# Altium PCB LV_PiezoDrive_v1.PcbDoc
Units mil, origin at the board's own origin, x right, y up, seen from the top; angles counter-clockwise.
Board outline 4800 x 6200 mil, 6 copper layers (Top Layer, Internal Plane 1, Internal Plane 2, Internal Plane 3, Internal Plane 4, Bottom Layer); 156 components, 66 nets, 491 pads, 10 vias.
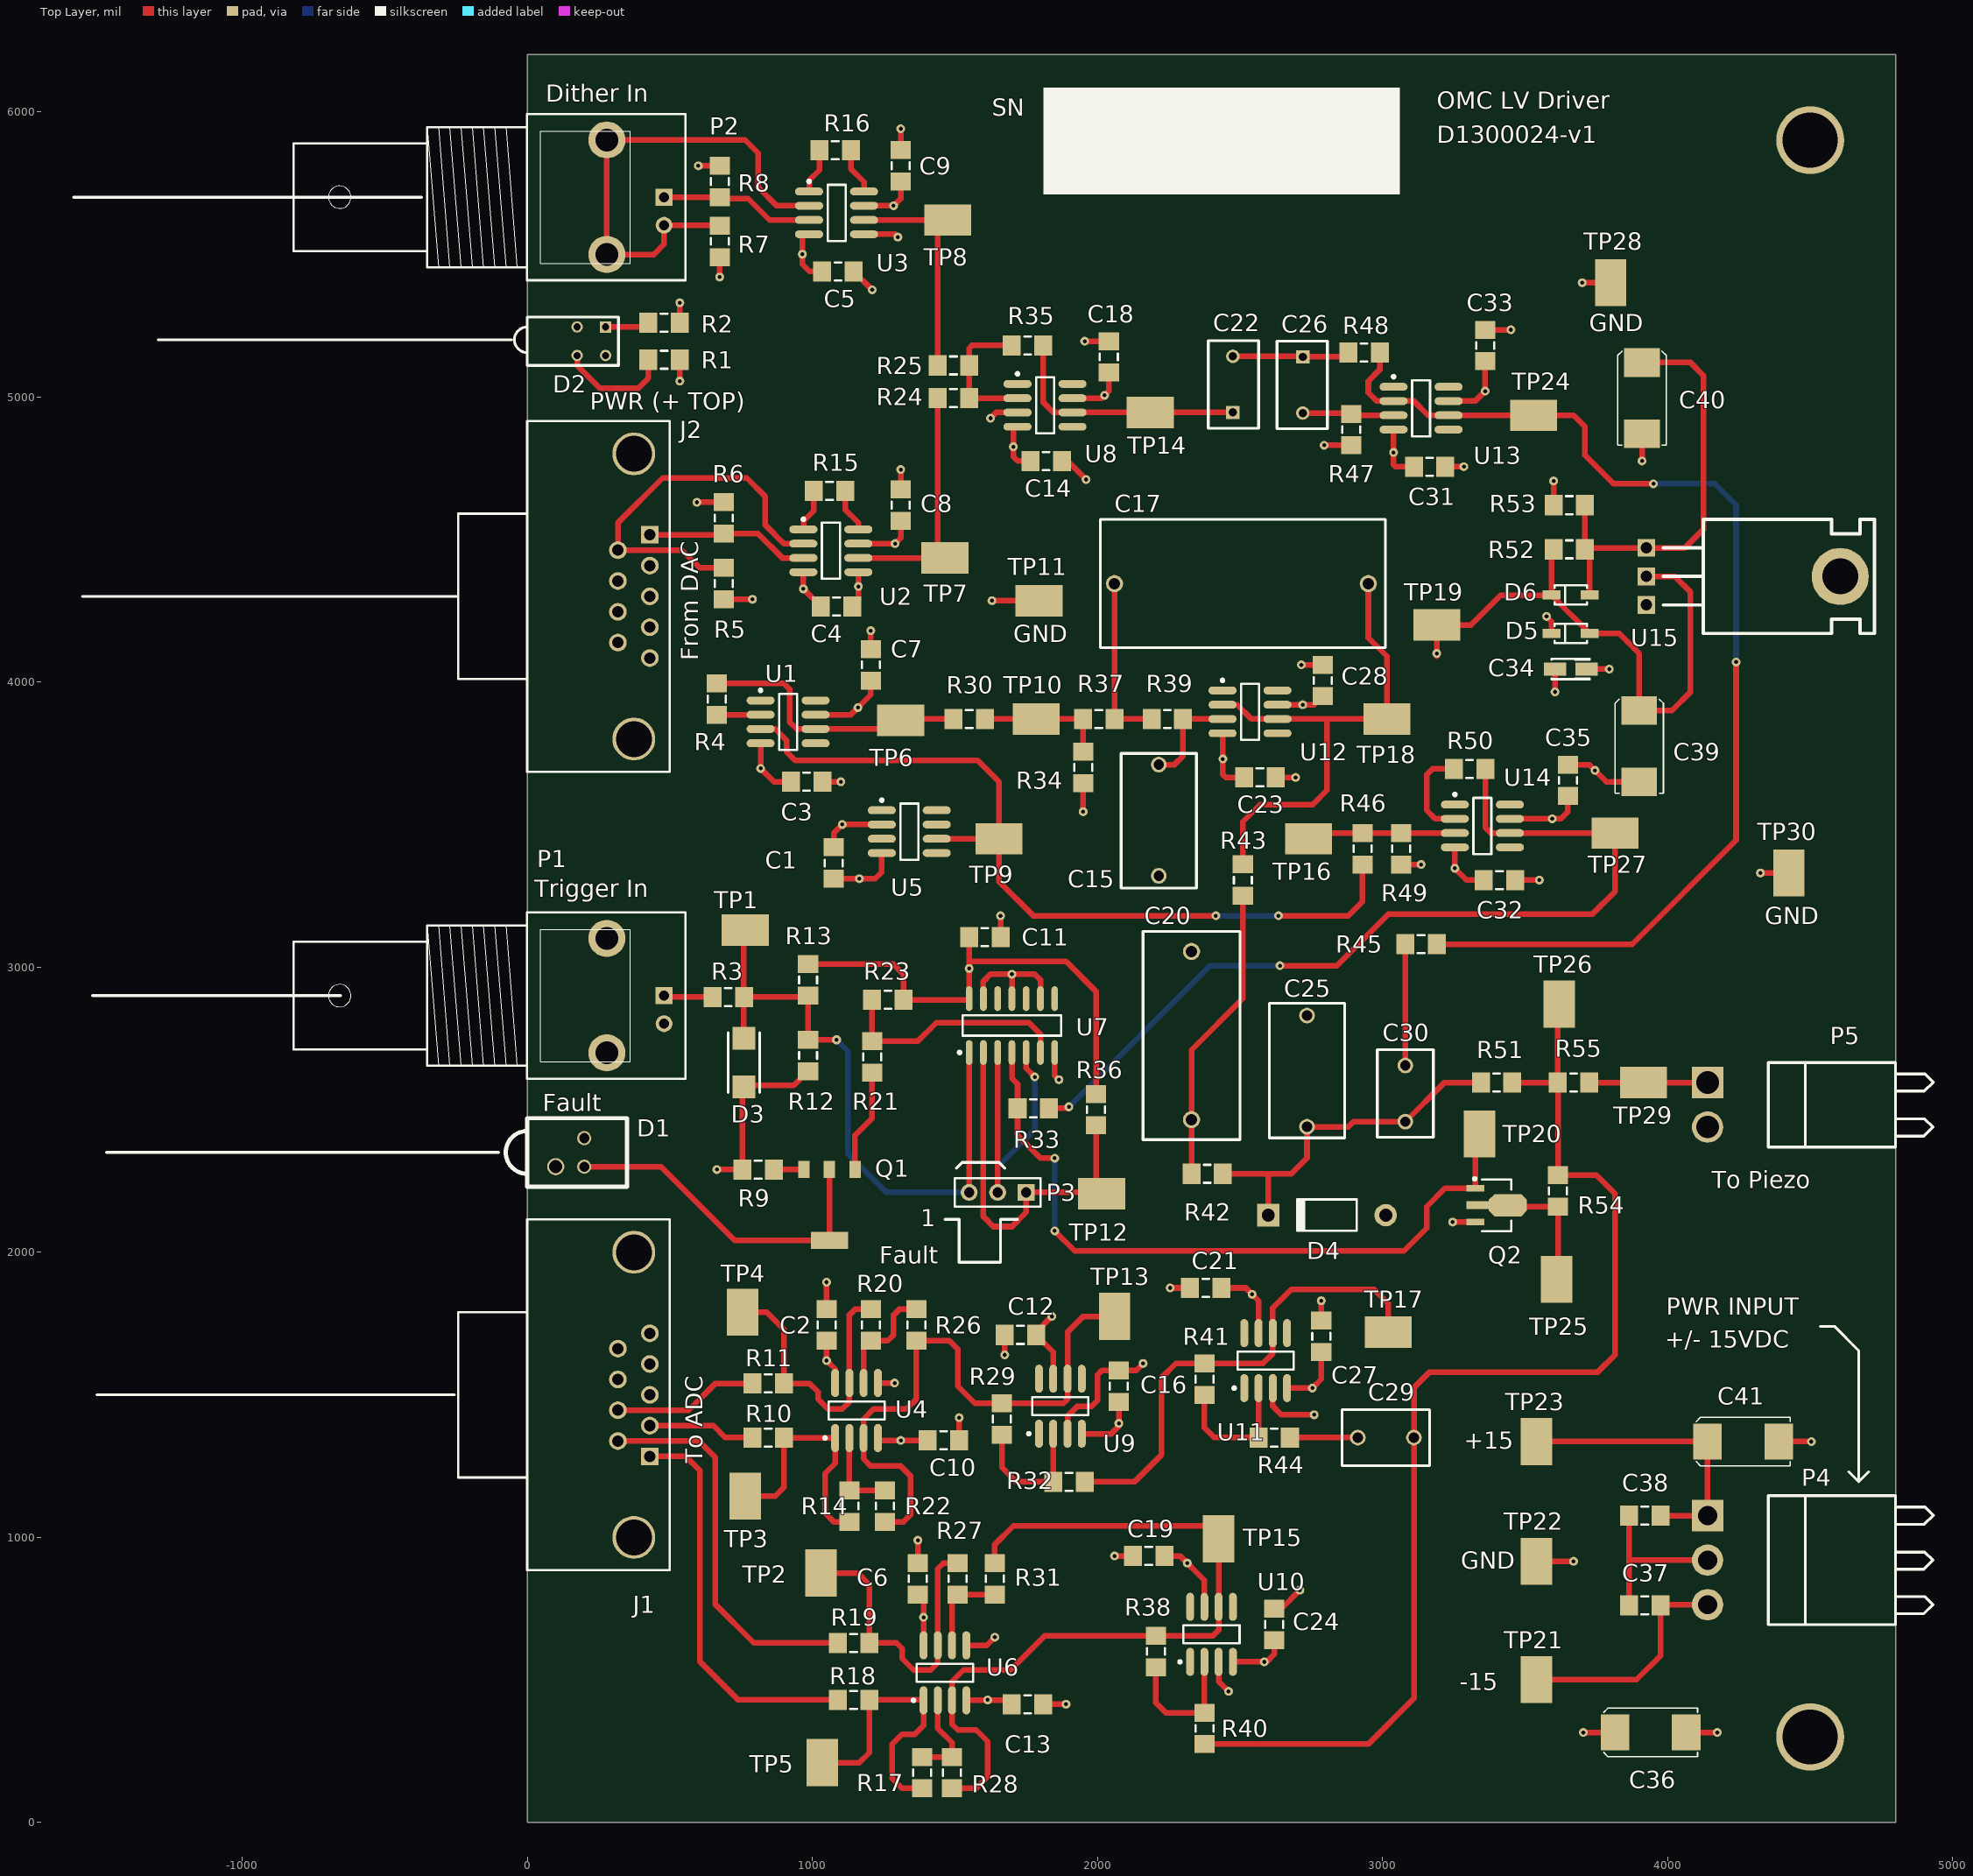
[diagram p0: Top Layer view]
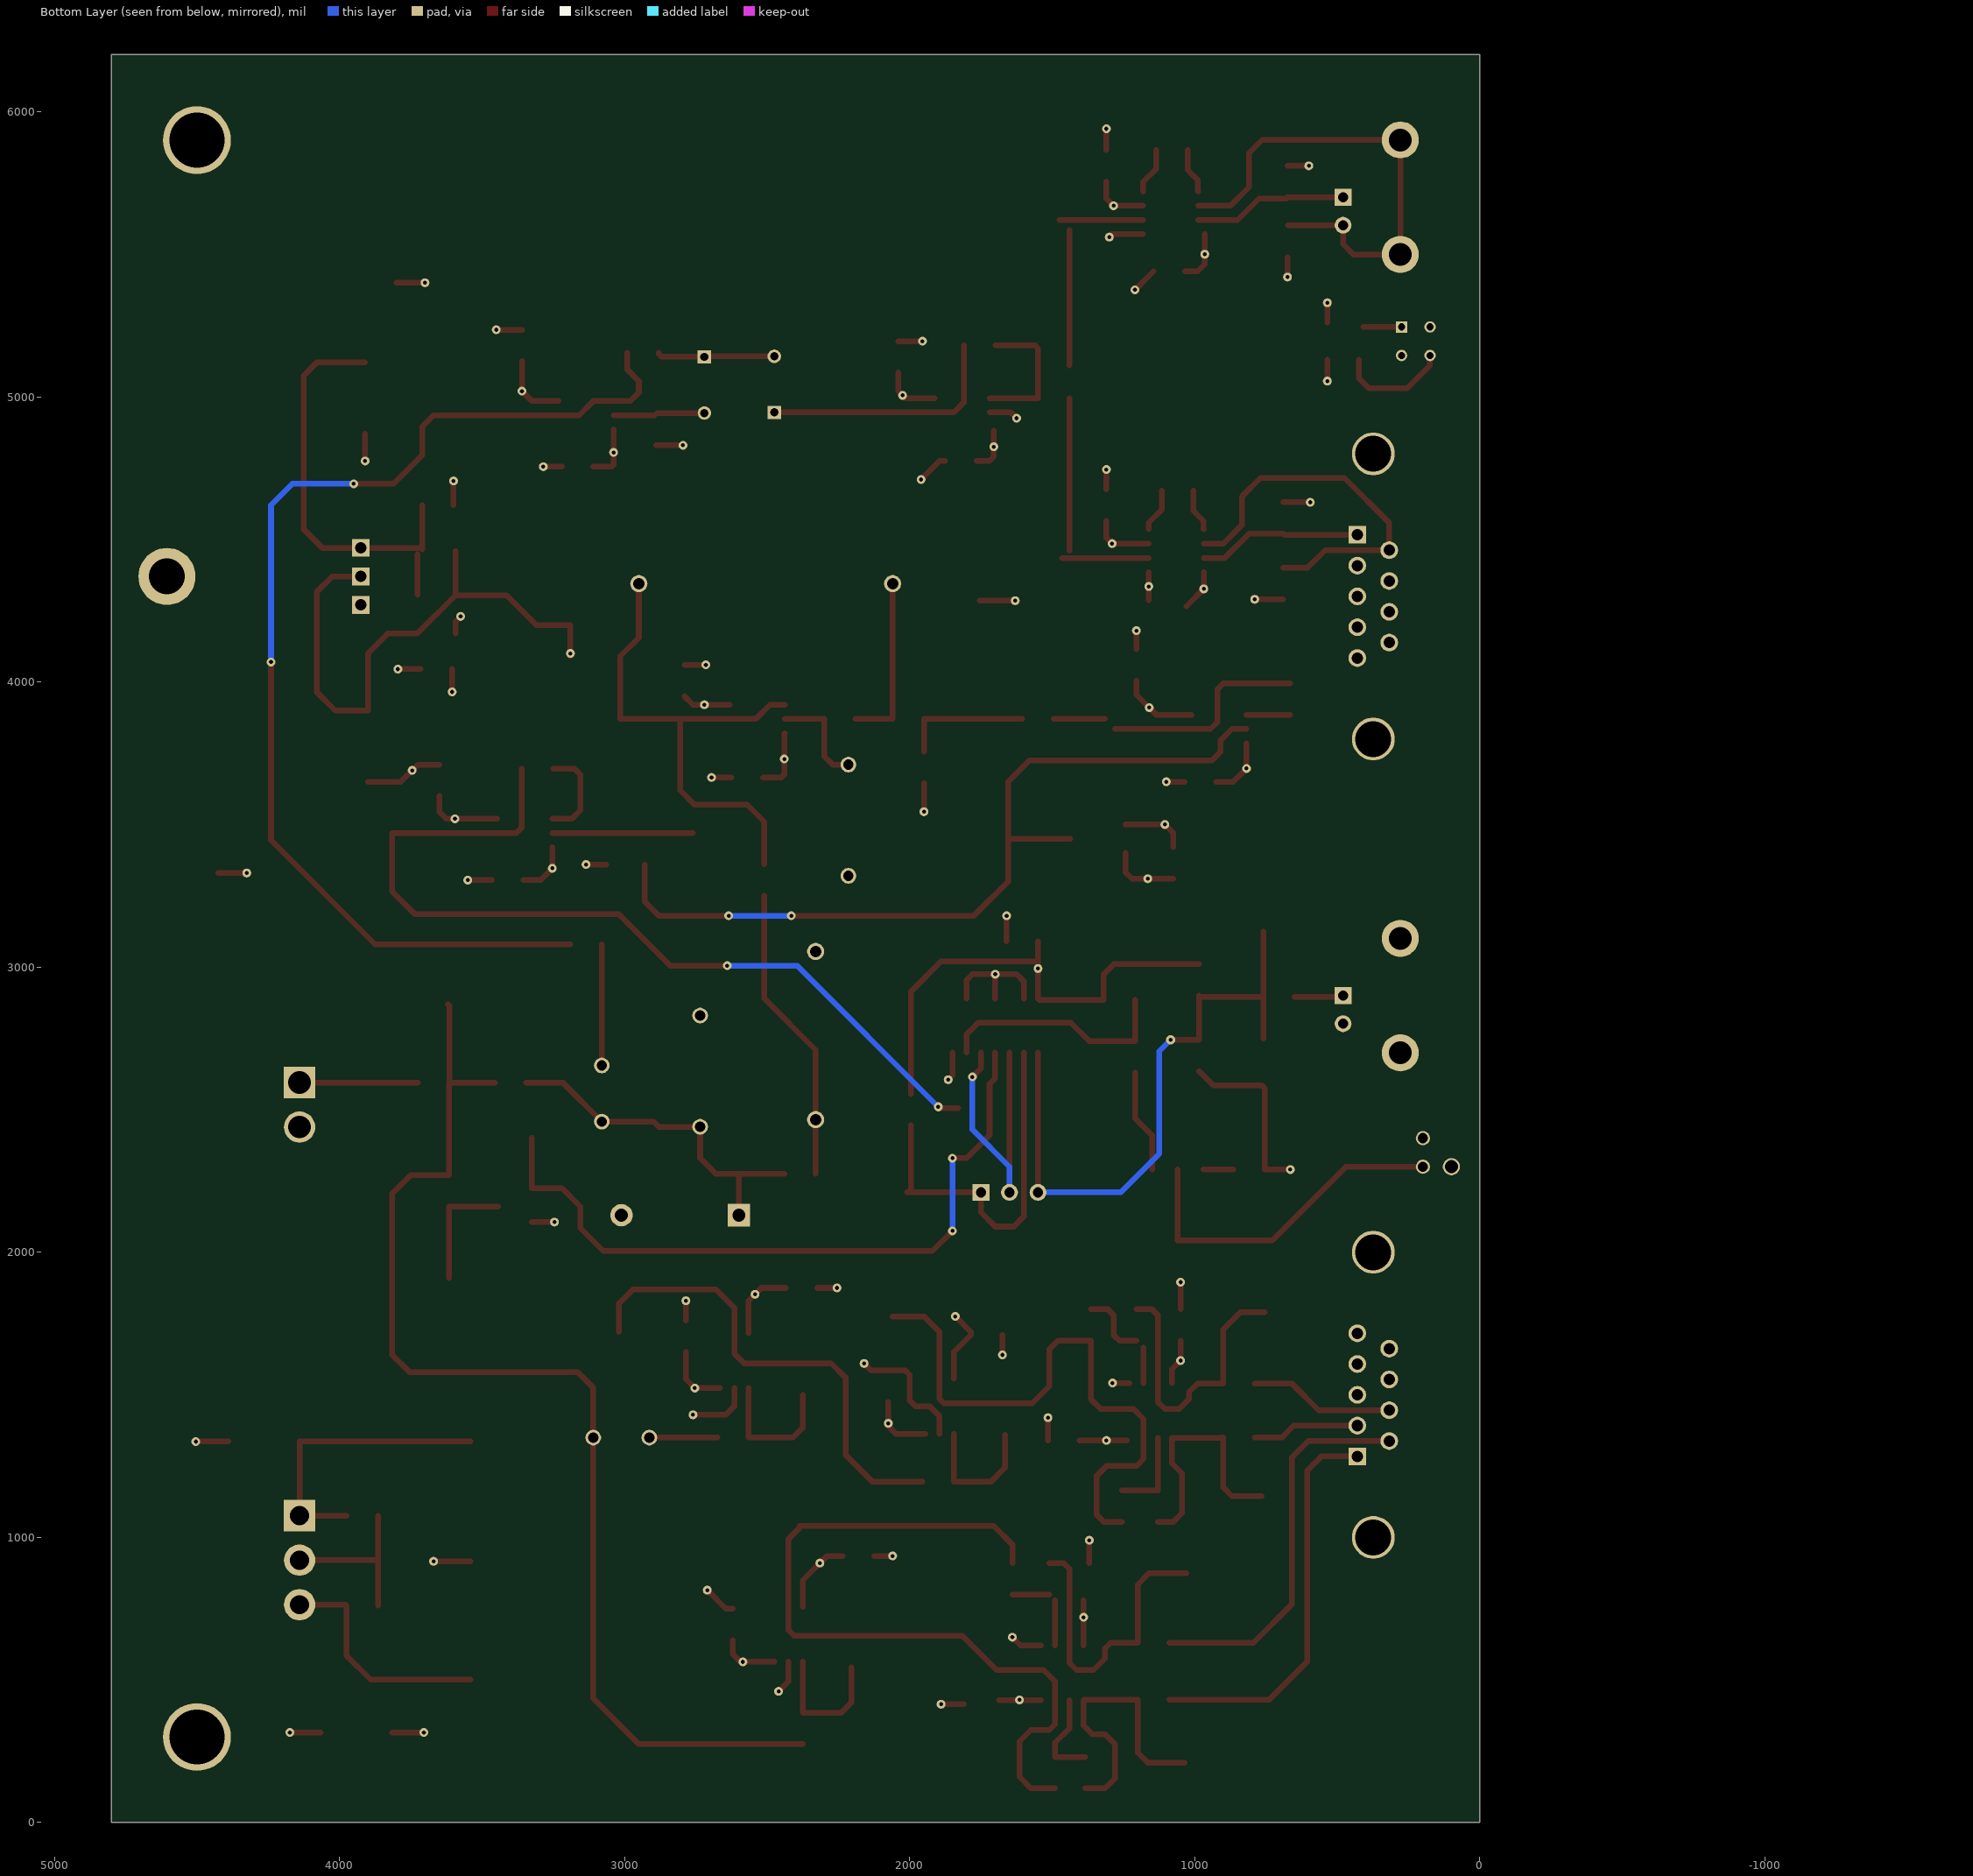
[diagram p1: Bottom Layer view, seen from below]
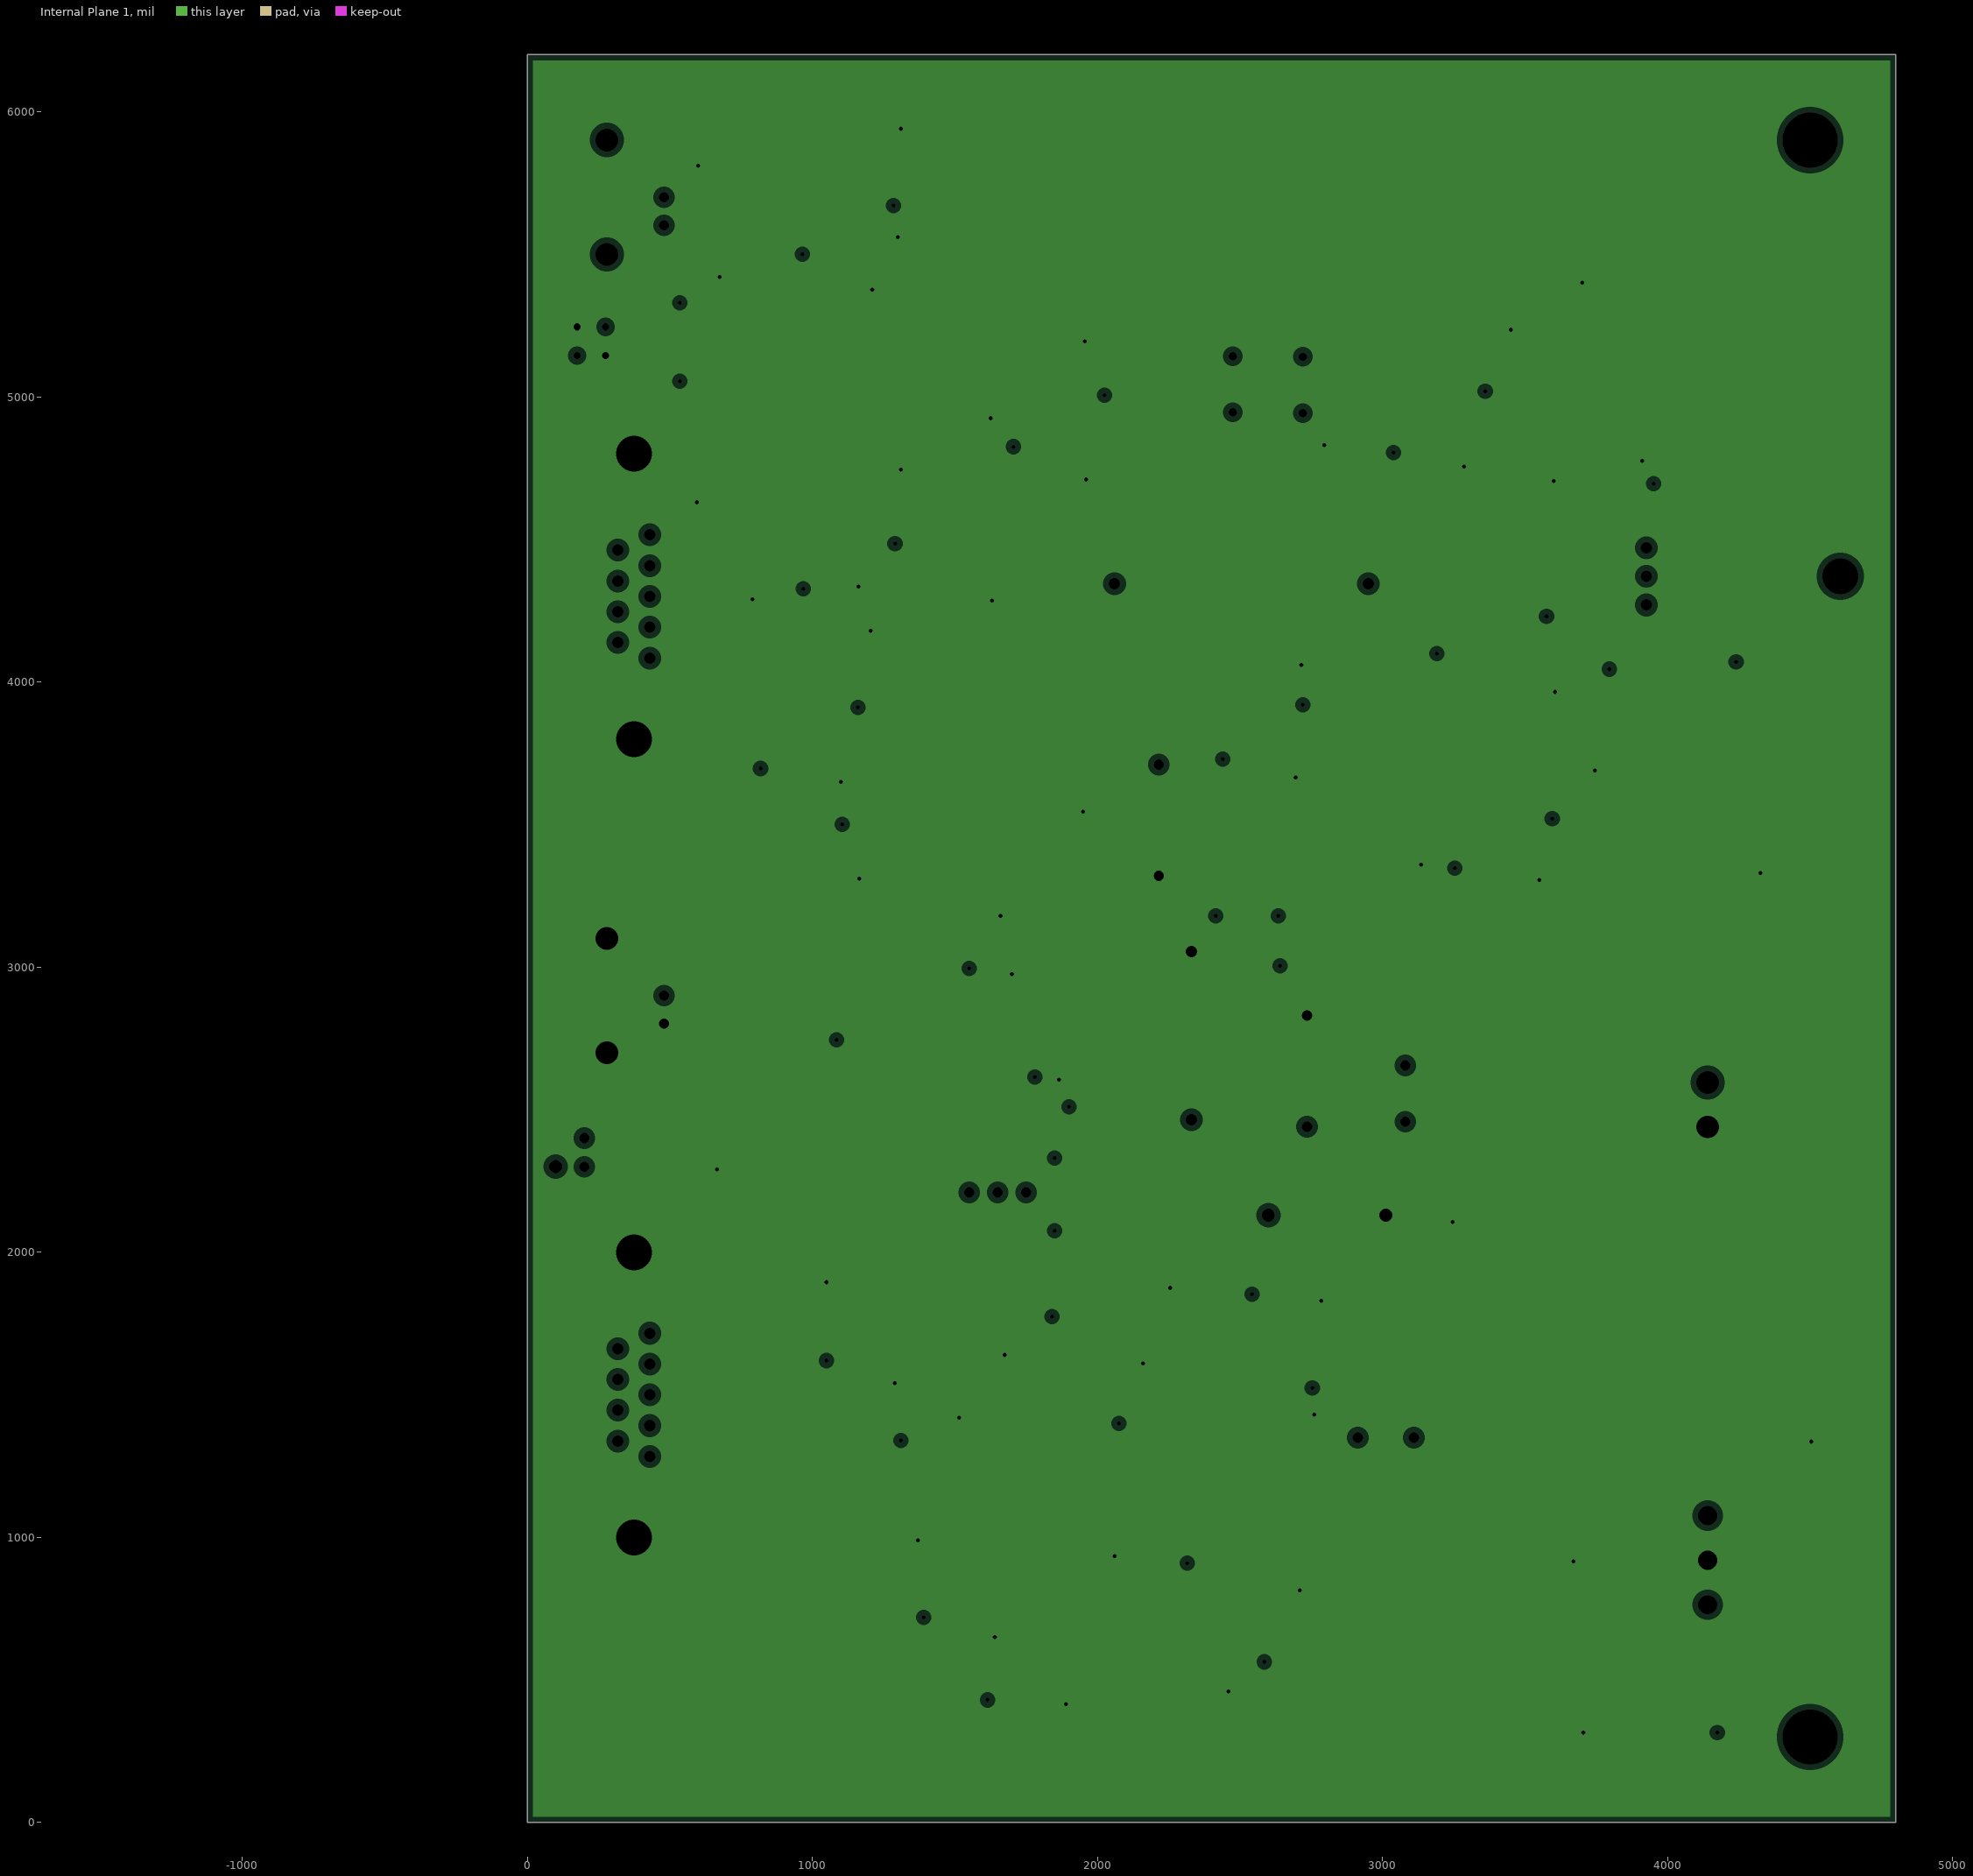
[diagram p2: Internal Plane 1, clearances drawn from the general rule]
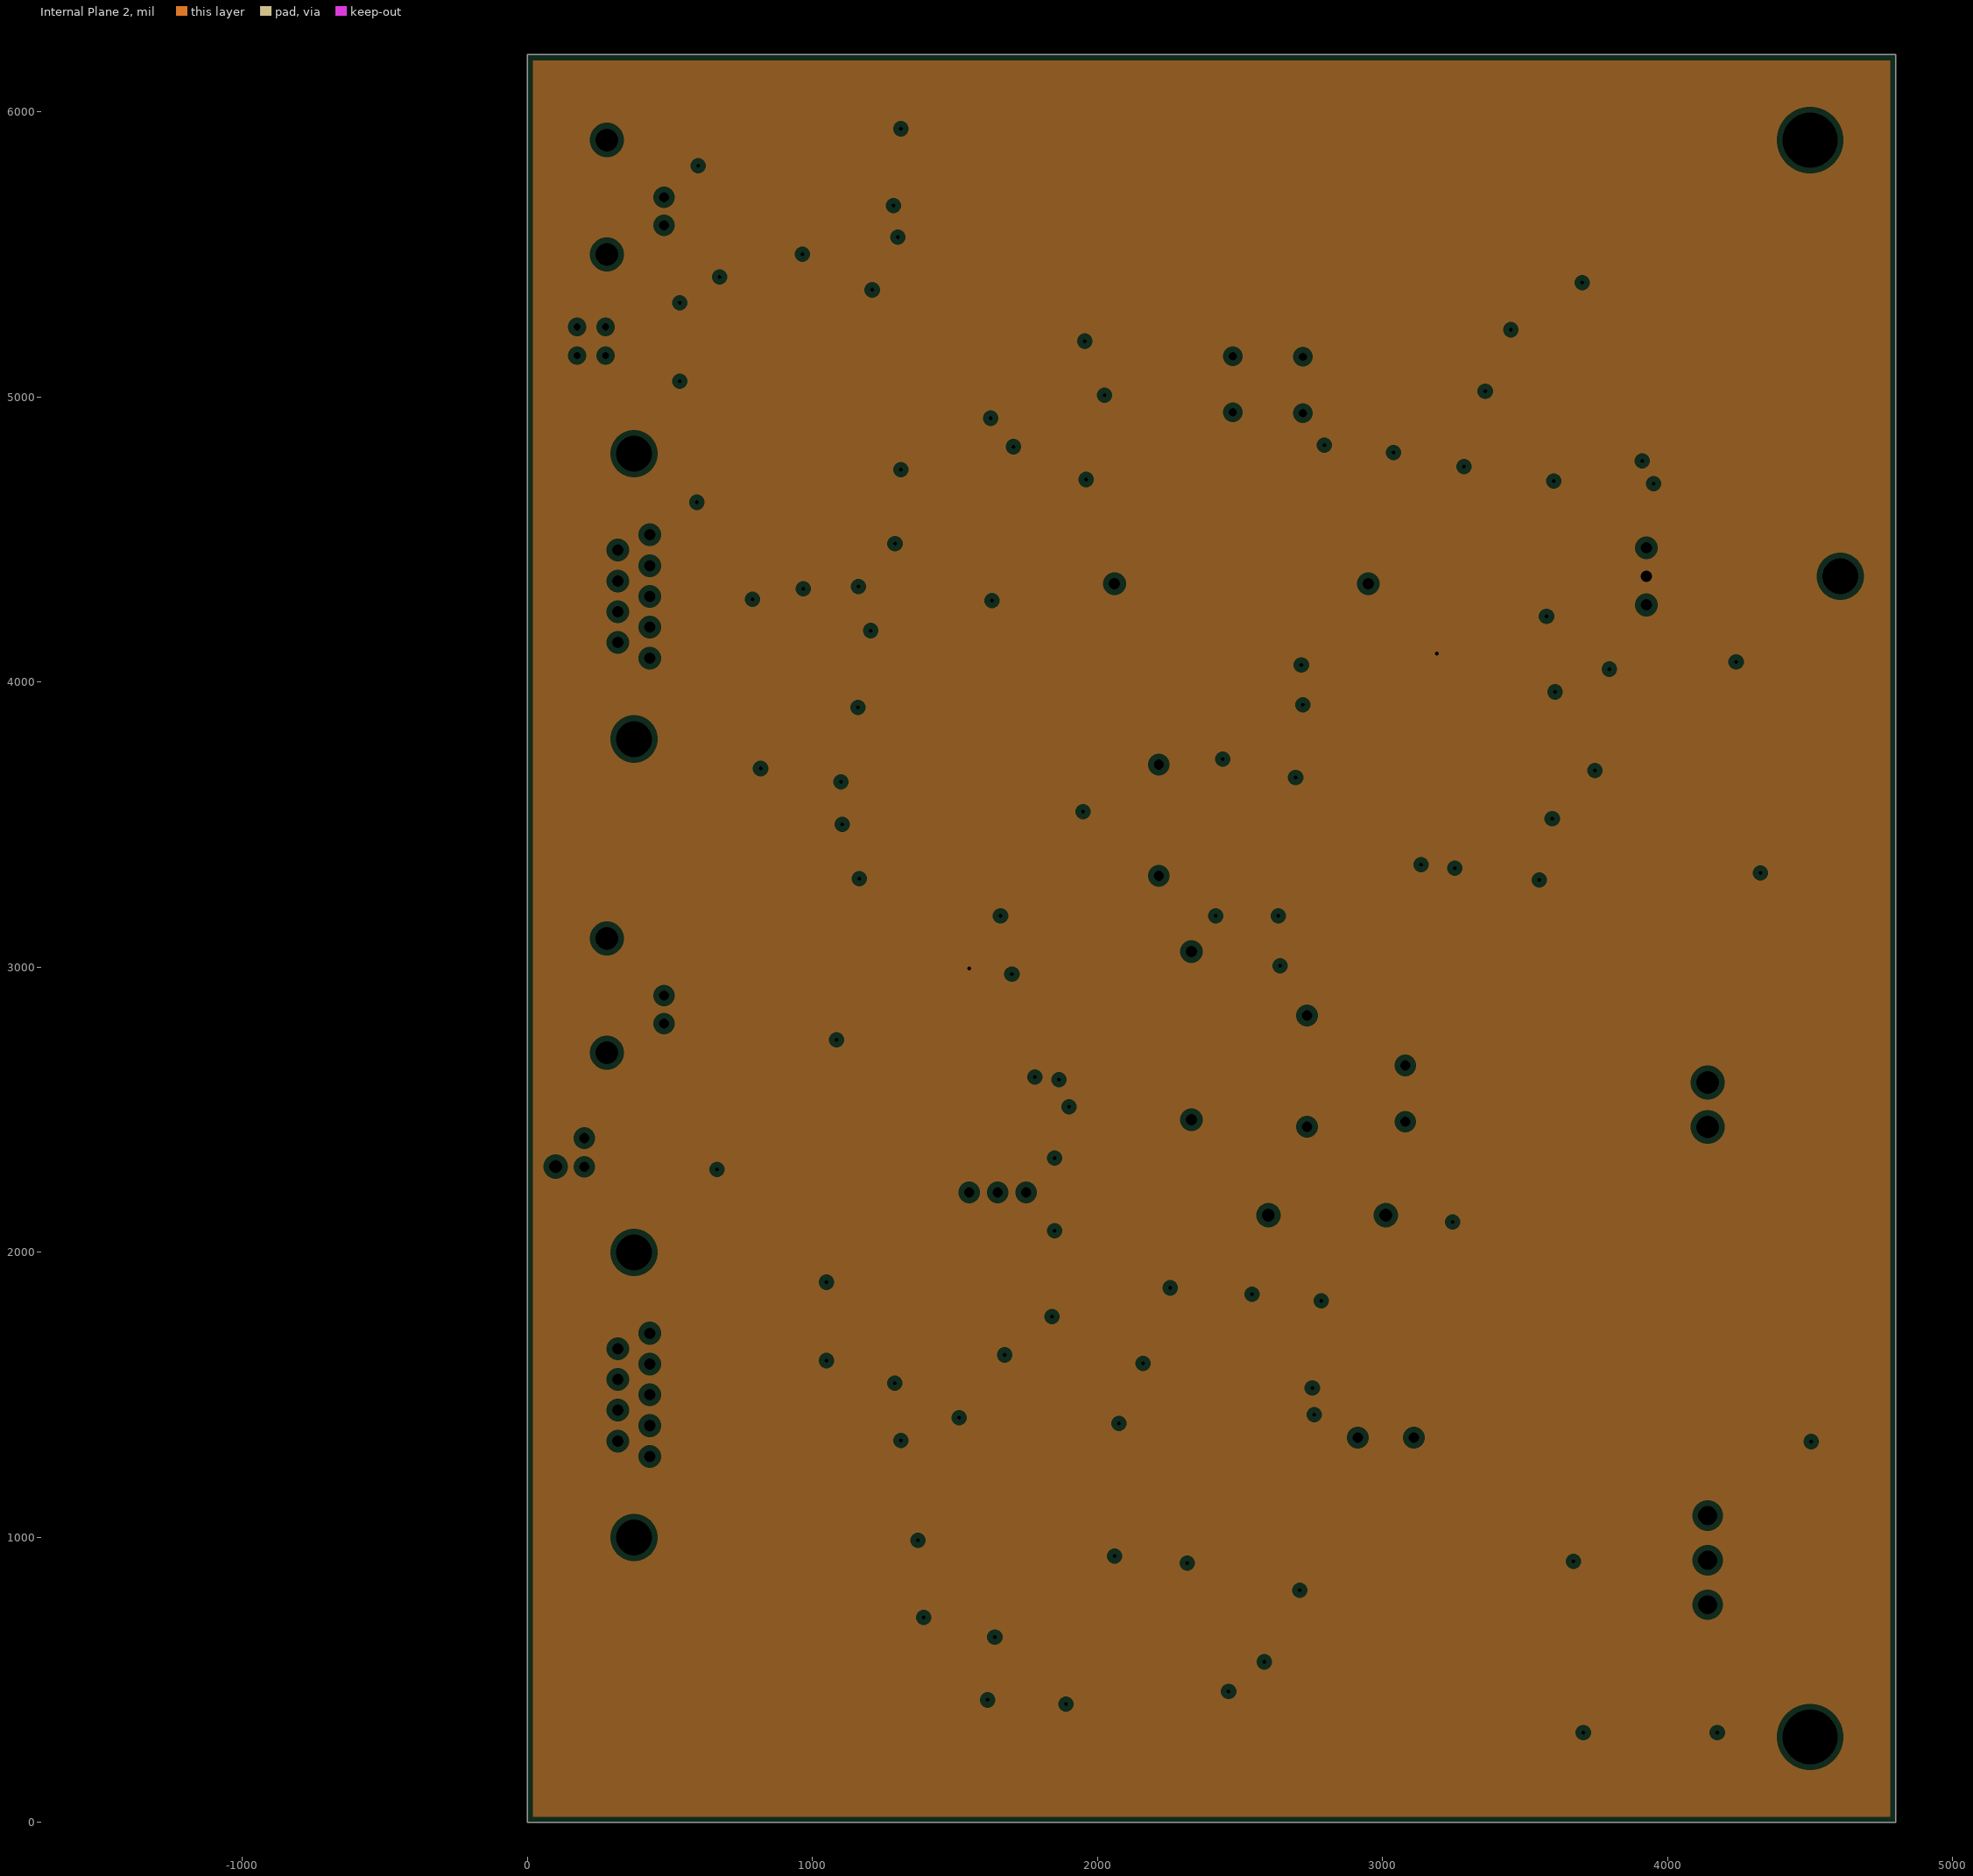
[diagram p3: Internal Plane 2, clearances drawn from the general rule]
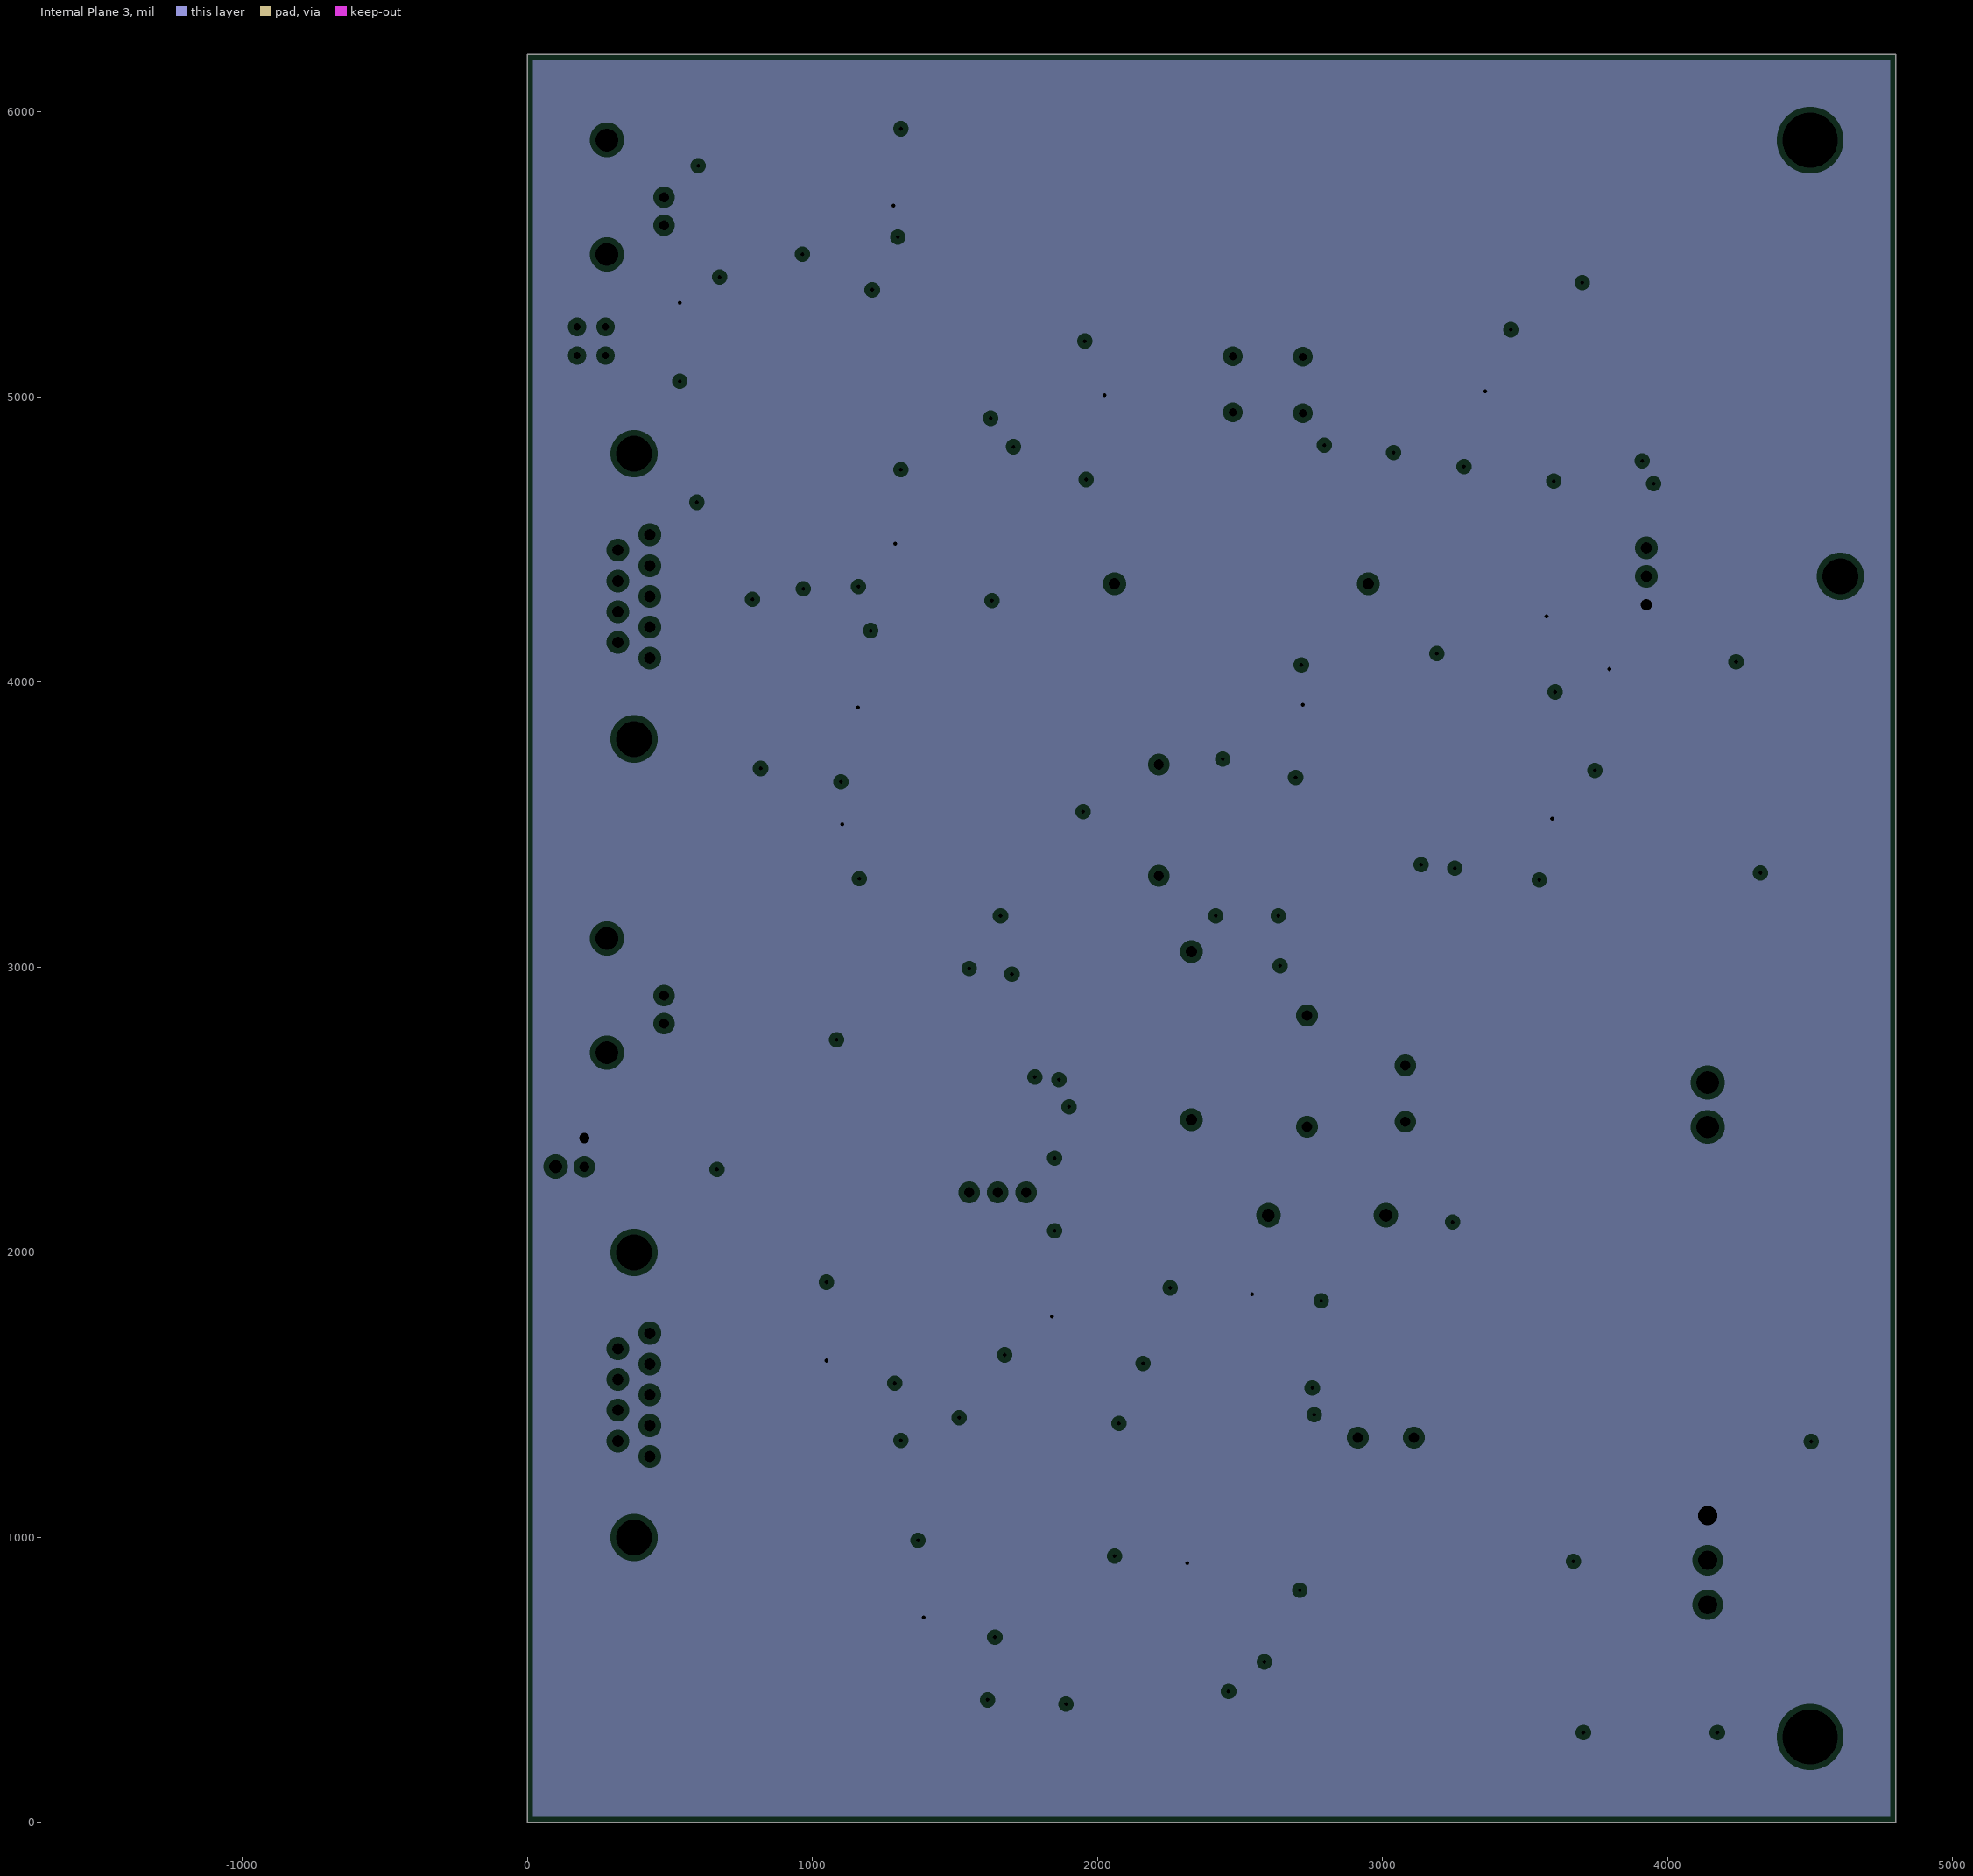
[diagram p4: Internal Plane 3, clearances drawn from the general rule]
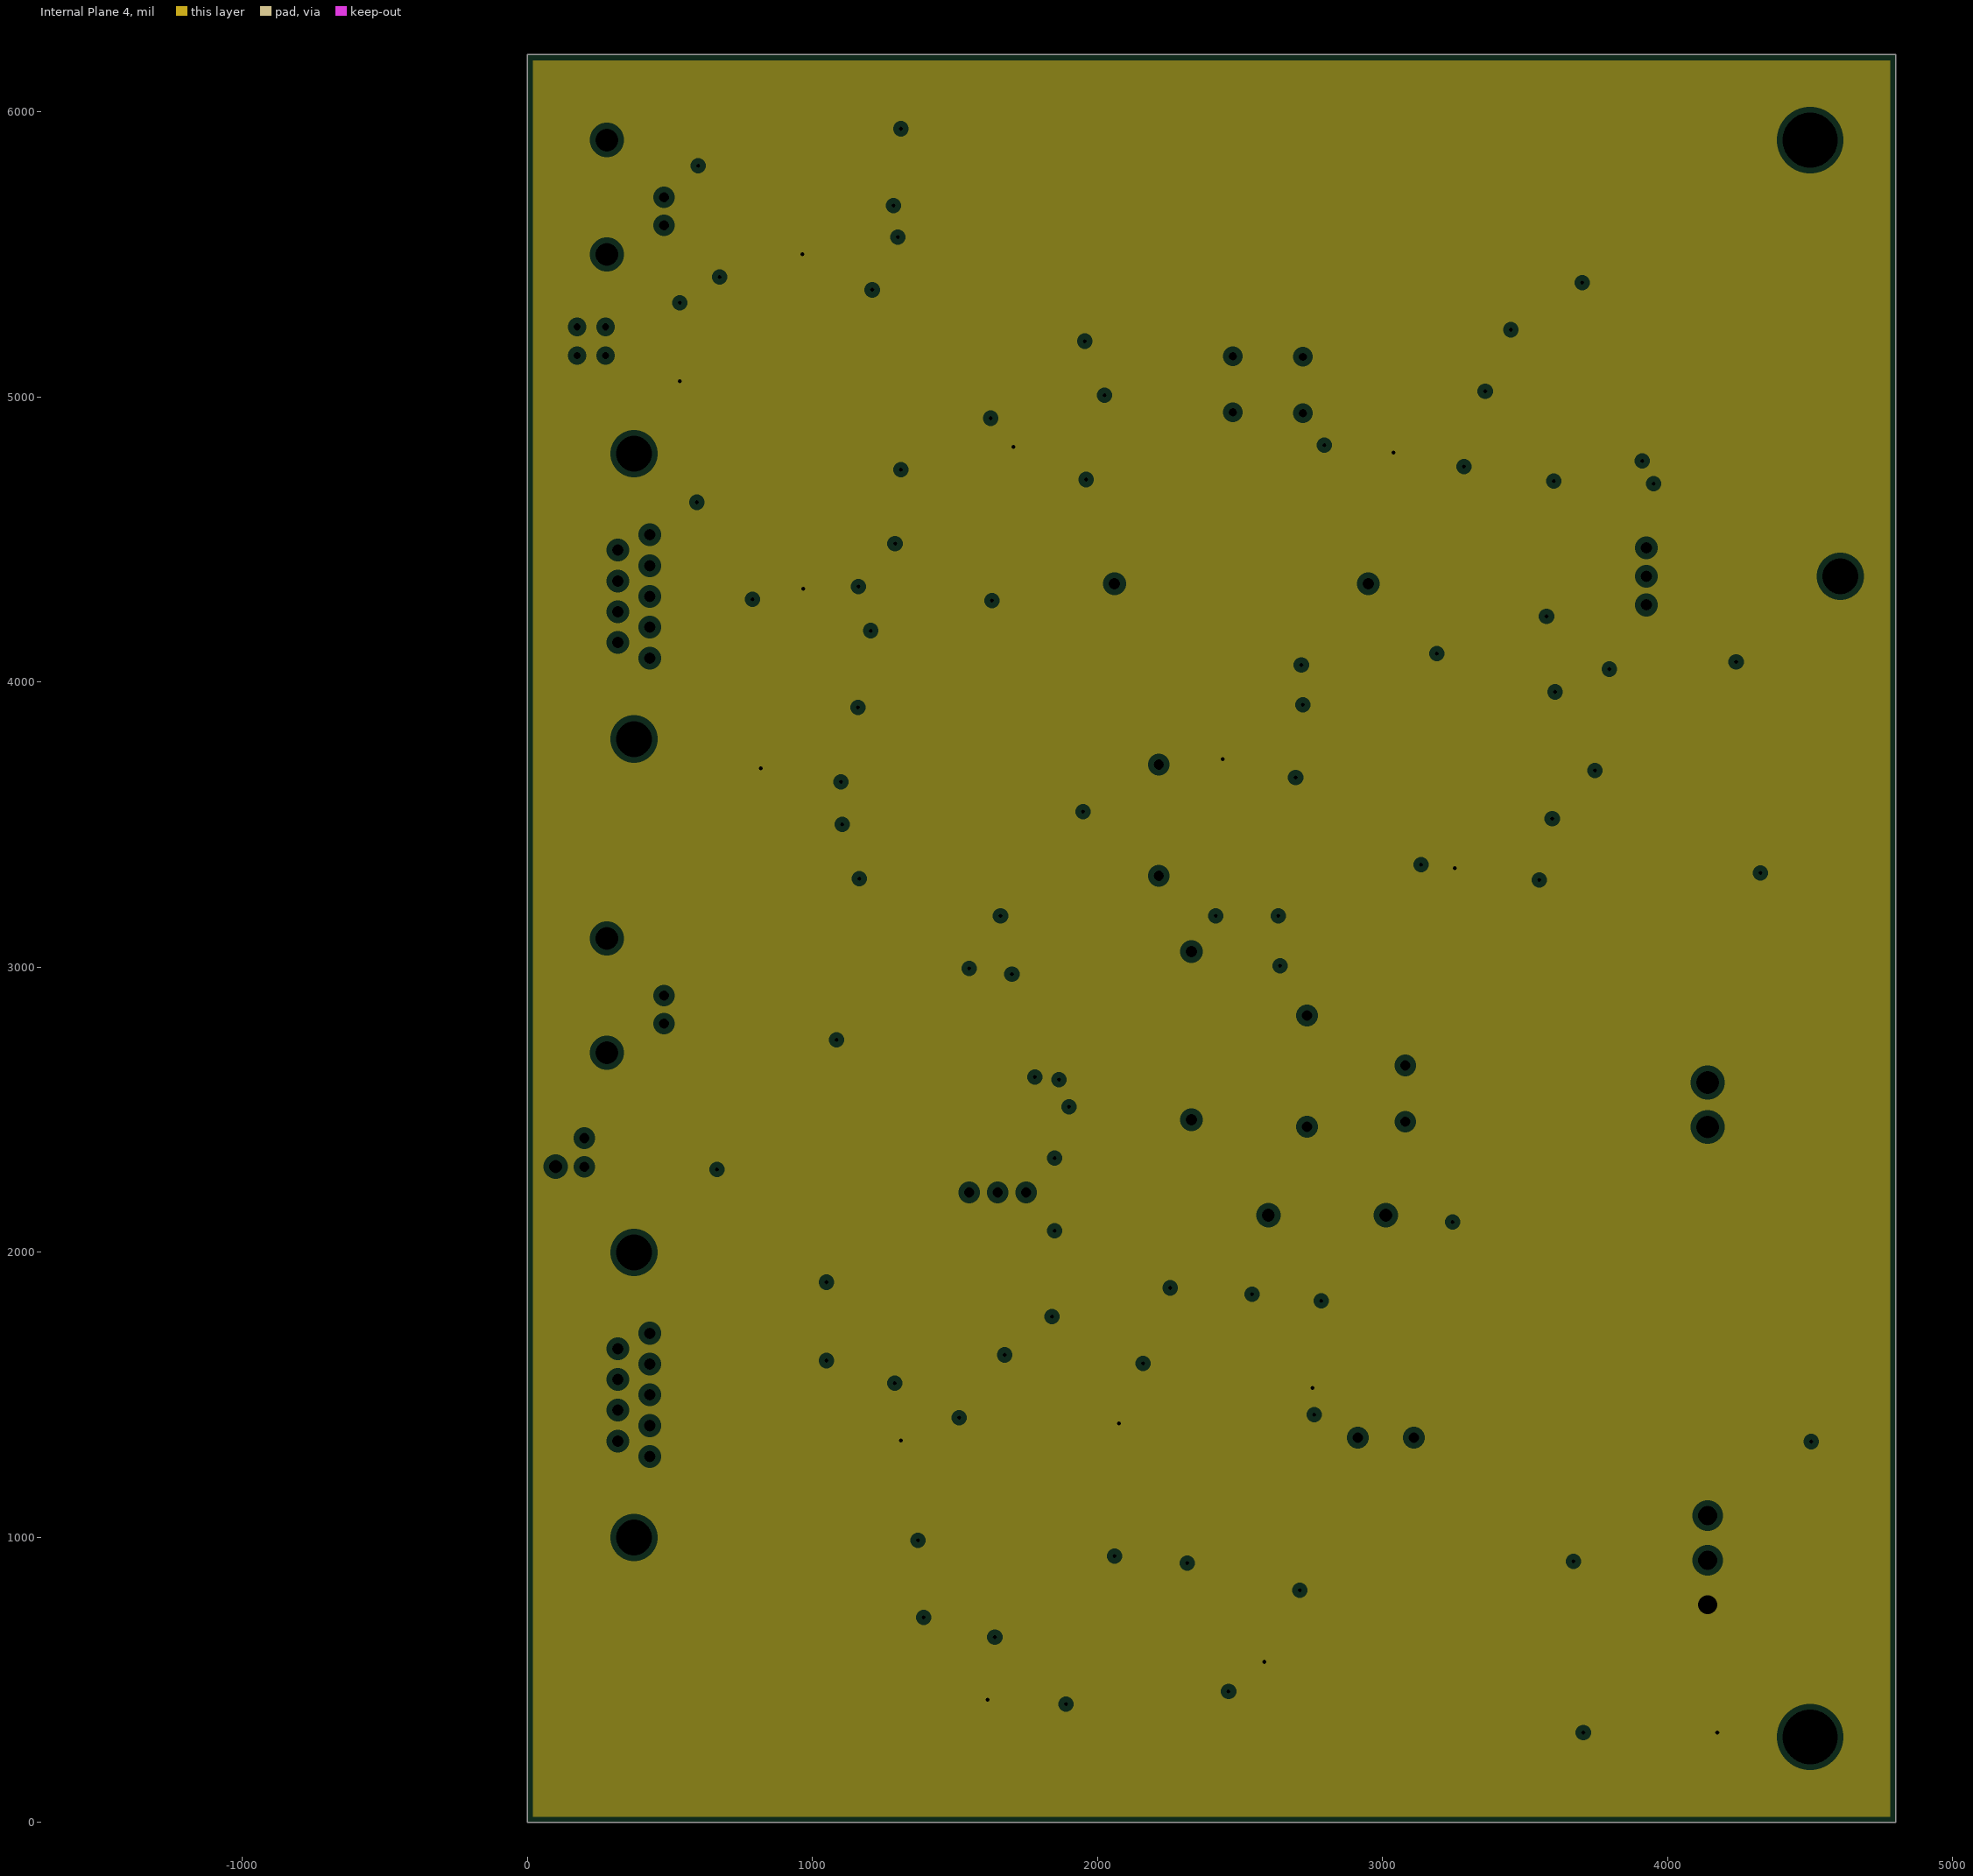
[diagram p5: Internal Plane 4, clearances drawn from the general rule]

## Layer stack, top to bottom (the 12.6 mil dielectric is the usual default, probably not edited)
Top Solder: solder mask 0.4, Solder Resist, Dk 3.5
Top Layer: signal copper 1.4
Dielectric1: core 12.6, FR-4, Dk 4.8
Internal Plane 1: plane copper 1.4
Dielectric2: prepreg 12.6, FR-4, Dk 4.8
Internal Plane 2: plane copper 1.4
Dielectric3: core 12.6, FR-4, Dk 4.8
Internal Plane 3: plane copper 1.4
Dielectric4: prepreg 12.6, FR-4, Dk 4.8
Internal Plane 4: plane copper 1.4
Dielectric5: core 12.6, FR-4, Dk 4.8
Bottom Layer: signal copper 1.4
Bottom Solder: solder mask 0.4, Solder Resist, Dk 3.5

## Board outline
0,0 0,6200 4800,6200 4800,0

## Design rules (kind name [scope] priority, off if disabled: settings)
Clearance [All] p1: gap=10 ignorepadtopadclearanceinfootprint=FALSE except(0: Arc-Hole Track-Hole SMDPad-Hole THPad-Hole Via-Hole Fill-Hole Poly-Hole Region-Hole Text-Hole)
HoleSize [All] p1: absolutevalues=TRUE maxlimit=200 minlimit=1 maxpercent=80.000 minpercent=20.000
MinimumSolderMaskSliver [All] p1: minsoldermaskwidth=6
PlaneClearance [All] p1: clearance=20
PlaneConnect [All] p1: planeconnectstyle=Relief reliefexpansion=20 reliefentries=4 reliefconductorwidth=10 reliefairgap=10
PolygonConnect [All] p1: connectstyle=Relief reliefconductorwidth=10 reliefentries=4 polygonreliefangle="90 Angle" airgapwidth=10
RoomDefinition LVPiezo_v1 [InComponentClass('LVPiezo_v1')] p1 off: confinementstyle=ConfineIn formatcopy=TRUE lockcomponents=FALSE outline -805,675 -515,675 -515,930 -805,930
RoutingVias [All] p1: holewidth=14 width=31 viastyle="Through Hole" minholewidth=14 minwidth=31 maxholewidth=40 maxwidth=50
SilkToSolderMaskClearance SilkscreenOverComponentPads [IsPad] p1: minsilkscreentomaskgap=4 clearancetoexposedcopper=TRUE
SolderMaskExpansion [All] p1: expansion=4
Width [All] p1: maxlimit=100 minlimit=10 preferedwidth=20
25 further rules are at their usual default settings.

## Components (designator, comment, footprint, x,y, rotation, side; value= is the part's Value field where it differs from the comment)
C1 "1UF" 3216[1206] 1075,3365 r270 top (schematic designator C27)
C2 "1UF" 3216[1206] 1050,1745 r270 top (schematic designator C4)
C3 "1UF" 3216[1206] 980,3650 r180 top (schematic designator C28)
C4 "1UF" 3216[1206] 1085,4265 r0 top (schematic designator C17)
C5 "1UF" 3216[1206] 1090,5440 r0 top (schematic designator C7)
C6 "1UF" 3216[1206] 1370,855 r270 top (schematic designator C13)
C7 "1UF" 3216[1206] 1205,4060 r270 top (schematic designator C24)
C8 "1UF" 3216[1206] 1310,4620 r90 top (schematic designator C10)
C9 "1UF" 3216[1206] 1310,5810 r90 top (schematic designator C3)
C10 "1UF" 3216[1206] 1460,1340 r180 top (schematic designator C6)
C11 "1UF" 3216[1206] 1605,3105 r0 top (schematic designator C41)
C12 "1UF" 3216[1206] 1730,1710 r0 top (schematic designator C9)
C13 "1UF" 3216[1206] 1755,415 r180 top (schematic designator C19)
C14 "1UF" 3216[1206] 1820,4775 r180 top (schematic designator C18)
C15 "1UF" ECQ-E1105KF 2215,3710 r270 top (schematic designator C26)
C16 "1UF" 3216[1206] 2075,1530 r270 top (schematic designator C2)
C17 "10UF" ECQ-E1106KF_Vert 2060,4345 r0 top (schematic designator C22)
C18 "1UF" 3216[1206] 2040,5140 r270 top (schematic designator C11)
C19 "1UF" 3216[1206] 2180,935 r0 top (schematic designator C16)
C20 "3.3UF" ECQ-E1335KF 2330,2465 r90 top (schematic designator C29)
C21 "1UF" 3216[1206] 2380,1875 r0 top (schematic designator C8)
C22 "47NF" ECQ-E1473KF 2475,4945 r90 top (schematic designator C14)
C23 "1UF" 3216[1206] 2570,3665 r180 top (schematic designator C25)
C24 "1UF" 3216[1206] 2620,695 r270 top (schematic designator C21)
C25 "1UF" ECQ-E1105KF 2735,2440 r90 top (schematic designator C30)
C26 "47NF" ECQ-E1473KF 2720,5140 r270 top (schematic designator C15)
C27 "1UF" 3216[1206] 2785,1705 r270 top (schematic designator C1)
C28 "1UF" 3216[1206] 2790,4005 r270 top (schematic designator C31)
C29 "0.47UF, Poly" ECQ-E1104KF 3110,1350 r180 top (schematic designator C5)
C30 "100pF, Poly" ECQ-E1104KF 3080,2655 r270 top (schematic designator C23)
C31 "1UF" 3216[1206] 3165,4755 r180 top (schematic designator C12)
C32 "1UF" 3216[1206] 3410,3305 r180 top (schematic designator C33)
C33 "1UF" 3216[1206] 3360,5180 r270 top (schematic designator C20)
C34 "1UF Tantalum, 50V" 3216 3660,4045 r180 top value=1uF (schematic designator C37)
C35 "1UF" 3216[1206] 3650,3655 r270 top (schematic designator C32)
C36 "10UF Tantalum, 35V" 7343-31 3815,316 r180 top (schematic designator C39)
C37 "0.1UF" 3216[1206] 3920,761 r180 top (schematic designator C40)
C38 "0.1UF" 3216[1206] 3920,1076 r180 top (schematic designator C35)
C39 "10UF Tantalum, 35V" 7343-31 3900,3900 r90 top value=10UF (schematic designator C36)
C40 "10UF Tantalum, 35V" 7343-31 3910,5120 r90 top value=10UF (schematic designator C38)
C41 "10UF Tantalum, 35V" 7343-31 4140,1336 r180 top (schematic designator C34)
D1 "MY_LED" LED_RA 0,2350 r270 top (schematic designator D5)
D2 "Stacked LED" "my LUMEX Dual LED" 275,5245 r0 top (schematic designator D7)
D3 "6V TVS" "DO-214AC (SMA)" 760,2710 r270 top (schematic designator D4)
D4 "Diode UF4007" DO-41 2805,2130 r180 top (schematic designator D3)
D5 "RB160M-60" SOD123 3660,4170 r180 top (schematic designator D6)
D6 "RB160M-60" SOD123 3660,4305 r180 top (schematic designator D8)
J1 "D9 Female" MY_DB9F_RA 430,1500 r90 top (schematic designator J2)
J2 "D9 Male" MY_DB9M_RA 430,4300 r90 top (schematic designator J1)
P1 "BNC" "BNC_RA CON" 480,2900 r0 top (schematic designator P2)
P2 "BNC" "BNC_RA CON" 480,5700 r0 top (schematic designator P1)
P3 "Header 3" HDR1X3 1750,2210 r180 top
P4 "Header 3H" Molex_156_RA_3 4140,1076 r0 top
P5 "Header 2" MOLEX_156_RA_2 4140,2595 r0 top
Q1 "PZT3904" SOT-223 1150,2290 r180 top (schematic designator Q2)
Q2 "RHP020N06" SOT89M 3400,2165 r0 top (schematic designator Q1)
R1 "1K" 3216[1206] 480,5130 r180 top (schematic designator R55)
R2 "1K" 3216[1206] 480,5260 r0 top (schematic designator R52)
R3 "10" 3216[1206] 705,2895 r0 top (schematic designator R47)
R4 "1K" 3216[1206] 665,3940 r90 top (schematic designator R31)
R5 "10K" 3216[1206] 690,4345 r90 top (schematic designator R24)
R6 "10K" 3216[1206] 690,4575 r270 top (schematic designator R18)
R7 "10K" 3216[1206] 675,5545 r90 top (schematic designator R6)
R8 "10K" 3216[1206] 675,5755 r270 top (schematic designator R3)
R9 "100" 3216[1206] 810,2290 r0 top (schematic designator R51)
R10 "0 Ohm" 3216[1206] 845,1350 r180 top (schematic designator R5)
R11 "0 Ohm" 3216[1206] 845,1540 r180 top (schematic designator R13)
R12 "10k" 3216[1206] 985,2690 r270 top (schematic designator R48)
R13 "OMIT" 3216[1206] 985,2955 r270 top (schematic designator R45)
R14 "4.99K" 3216[1206] 1130,1110 r270 top (schematic designator R2)
R15 "OMIT" 3216[1206] 1060,4670 r180 top (schematic designator R17)
R16 "OMIT" 3216[1206] 1080,5865 r180 top (schematic designator R1)
R17 "4.99K" 3216[1206] 1385,175 r270 top (schematic designator R19)
R18 "0 Ohm" 3216[1206] 1145,430 r180 top (schematic designator R26)
R19 "0 Ohm" 3216[1206] 1145,630 r180 top (schematic designator R30)
R20 "4.99K" 3216[1206] 1205,1745 r90 top (schematic designator R9)
R21 "1K" 3216[1206] 1210,2685 r270 top (schematic designator R50)
R22 "4.99K" 3216[1206] 1255,1110 r90 top (schematic designator R4)
R23 "10k" 3216[1206] 1265,2885 r180 top (schematic designator R49)
R24 "1K" 3216[1206] 1495,4995 r0 top (schematic designator R21)
R25 "1K" 3216[1206] 1495,5110 r180 top (schematic designator R14)
R26 "4.99K" 3216[1206] 1365,1745 r90 top (schematic designator R10)
R27 "4.99K" 3216[1206] 1510,855 r90 top (schematic designator R28)
R28 "4.99K" 3216[1206] 1490,175 r90 top (schematic designator R23)
R29 "100K" 3216[1206] 1665,1415 r90 top (schematic designator R12)
R30 "0 Ohm" 3216[1206] 1550,3870 r0 top (schematic designator R32)
R31 "4.99K" 3216[1206] 1640,855 r270 top (schematic designator R29)
R32 "4.99K" 3216[1206] 1900,1195 r0 top (schematic designator R8)
R33 "10k" 3216[1206] 1775,2505 r180 top (schematic designator R44)
R34 "OMIT" 3216[1206] 1950,3700 r270 top (schematic designator R39)
R35 "1K" 3216[1206] 1755,5180 r0 top (schematic designator R15)
R36 "10k" 3216[1206] 1995,2500 r270 top (schematic designator R46)
R37 "21.5K" 3216[1206] 2005,3870 r180 top (schematic designator R33)
R38 "1M" 3216[1206] 2205,600 r90 top (schematic designator R20)
R39 "1.21K" 3216[1206] 2245,3870 r180 top (schematic designator R34)
R40 "1M" 3216[1206] 2375,330 r90 top (schematic designator R27)
R41 "10K" 3216[1206] 2375,1555 r90 top (schematic designator R11)
R42 "10k" 3216[1206] 2385,2275 r0 top (schematic designator R36)
R43 "10k" 3216[1206] 2510,3305 r270 top (schematic designator R35)
R44 "1K" 3216[1206] 2620,1350 r0 top (schematic designator R7)
R45 "75" 3216[1206] 3135,3080 r0 top (schematic designator R22)
R46 "0 Ohm" 3216[1206] 2930,3415 r90 top (schematic designator R42)
R47 "909" 3216[1206] 2890,4885 r270 top (schematic designator R25)
R48 "453" 3216[1206] 2935,5155 r180 top (schematic designator R16)
R49 "10k" 3216[1206] 3065,3415 r270 top (schematic designator R43)
R50 "1K" 3216[1206] 3305,3695 r0 top (schematic designator R40)
R51 "10" 3216[1206] 3400,2595 r180 top (schematic designator R37)
R52 "249" 3216[1206] 3655,4465 r180 top (schematic designator R53)
R53 "732" 3216[1206] 3655,4620 r0 top (schematic designator R54)
R54 "1 ohm" 3216[1206] 3615,2215 r90 top (schematic designator R41)
R55 "0 Ohm" 3216[1206] 3670,2595 r0 top (schematic designator R38)
TP1 "TESTPT" smt_tp 765,3130 r0 top (schematic designator TP23)
TP2 "TESTPT" smt_tp 1030,875 r90 top (schematic designator TP11)
TP3 "TESTPT" smt_tp 765,1145 r90 top (schematic designator TP1)
TP4 "TESTPT" smt_tp 755,1790 r90 top (schematic designator TP3)
TP5 "TESTPT" smt_tp 1035,210 r90 top (schematic designator TP6)
TP6 "TESTPT" smt_tp 1310,3865 r180 top (schematic designator TP13)
TP7 "TESTPT" smt_tp 1465,4435 r0 top
TP8 "TESTPT" smt_tp 1475,5620 r0 top (schematic designator TP2)
TP9 "TESTPT" smt_tp 1655,3450 r180 top (schematic designator TP15)
TP10 "TESTPT" smt_tp 1785,3870 r180 top (schematic designator TP14)
TP11 "TESTPT" smt_tp 1795,4285 r180 top (schematic designator TP30)
TP12 "TESTPT" smt_tp 2015,2205 r180 top (schematic designator TP24)
TP13 "TESTPT" smt_tp 2060,1775 r90 top (schematic designator TP5)
TP14 "TESTPT" smt_tp 2185,4945 r0 top (schematic designator TP8)
TP15 "TESTPT" smt_tp 2425,995 r90 top (schematic designator TP10)
TP16 "TESTPT" smt_tp 2740,3450 r180 top (schematic designator TP20)
TP17 "TESTPT" smt_tp 3020,1720 r180 top (schematic designator TP4)
TP18 "TESTPT" smt_tp 3015,3870 r180 top (schematic designator TP12)
TP19 "TESTPT" smt_tp 3190,4200 r180 top (schematic designator TP28)
TP20 "TESTPT" smt_tp 3340,2415 r270 top (schematic designator TP22)
TP21 "TESTPT" smt_tp 3540,501 r90 top (schematic designator TP32)
TP22 "TESTPT" smt_tp 3540,916 r90 top (schematic designator TP26)
TP23 "TESTPT" smt_tp 3540,1336 r90 top (schematic designator TP25)
TP24 "TESTPT" smt_tp 3530,4935 r0 top (schematic designator TP9)
TP25 "TESTPT" smt_tp 3610,1905 r270 top (schematic designator TP21)
TP26 "TESTPT" smt_tp 3620,2870 r90 top (schematic designator TP17)
TP27 "TESTPT" smt_tp 3815,3470 r180 top (schematic designator TP19)
TP28 "TESTPT" smt_tp 3800,5400 r90 top (schematic designator TP31)
TP29 "TESTPT" smt_tp 3915,2595 r180 top (schematic designator TP18)
TP30 "TESTPT" smt_tp 4425,3330 r90 top (schematic designator TP29)
U1 "ADOP27AQ" SO8_M 915,3860 r0 top (schematic designator U12)
U2 "AD620" SO8_M 1065,4460 r0 top (schematic designator U5)
U3 "AD620" SO8_M 1085,5645 r0 top
U4 "AD8672" so8_m 1155,1445 r90 top
U5 "LT1021U" SO8_M 1340,3475 r0 top (schematic designator U11)
U6 "AD8672" so8_m 1465,525 r90 top (schematic designator U8)
U7 "SN74LS06D" D014_N 1700,2795 r90 top (schematic designator U14)
U8 "ADOP27AQ" SO8_M 1816,4970 r0 top (schematic designator U7)
U9 "ADOP27AQ" SO8_M 1870,1460 r90 top (schematic designator U2)
U10 "ADOP27AQ" SO8_M 2400,660 r90 top (schematic designator U9)
U11 "ADOP27AQ" SO8_M 2590,1620 r90 top (schematic designator U1)
U12 "ADOP27AQ" SO8_M 2535,3895 r0 top (schematic designator U10)
U13 "ADOP27AQ" SO8_M 3135,4960 r0 top (schematic designator U6)
U14 "ADOP27AQ" SO8_M 3350,3495 r0 top (schematic designator U13)
U15 "LM317T" MY_TO220 3925,4370 r270 top

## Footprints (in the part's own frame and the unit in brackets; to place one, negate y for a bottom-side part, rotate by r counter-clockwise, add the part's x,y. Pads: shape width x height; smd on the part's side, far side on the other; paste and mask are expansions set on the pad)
3216 [mm] "Capacitor, SM Tantalum; Body 3.2 x 1.6 mm (LxW typ)"
  rect 2x1.2 smd: 1(-1.4,0) 2(1.4,0)
  silkscreen extent -1.7,-0.9 1.7,0.9
3216[1206] [mm] "Chip Resistor; Body 3.2 x 1.6 mm (LxW typ)"
  rect 1.6x1.8 smd: 1(-1.4,0) 2(1.4,0)
  silkscreen extent -0.3,-0.8 0.3,0.8, body extent -2.29,-1.02 2.29,1.02, height 0.48
7343-31 [mil]
  rect 100x125 smd: 1(0,0) 2(-250,0)
  silkscreen extent -290,-85 40,85
"BNC_RA CON" [mm] "Connector; BNC Elbow"
  rect 1.5x1.5 hole 0.914: 1(0,0)
  round 3.3 hole 2.032: 2(-5.1,-5.1) 2(-5.1,5.1)
  round 1.5 hole 0.914: 2(0,-2.5)
  silkscreen extent -33,-7.4 1.9,7.4
D014_N [mm] "14-Pin Small Outline Integrated Circuit 1.27 mm Pitch, IPC Medium Density"
  oval 2.2x0.6 smd: 1(-2.4,3.81) 2(-2.4,2.54) 3(-2.4,1.27) 4(-2.4,0) 5(-2.4,-1.27) 6(-2.4,-2.54) 7(-2.4,-3.81) 8(2.4,-3.81) 9(2.4,-2.54) 10(2.4,-1.27) 11(2.4,0) 12(2.4,1.27) 13(2.4,2.54) 14(2.4,3.81)
  silkscreen extent -2.52,-4.4 0.9,4.78, body extent -1.95,-4.33 1.95,4.33, height 1.75
DO-41 [mm] "Diode, Axial; Body 5.2 x 2.7 mm (LxDia. max), Lead Dia. 0.86 mm (max)"
  round 2 hole 1.168: 1(-5.23,0)
  rect 2x2 hole 1.168: 2(5.23,0)
  silkscreen extent -2.65,-1.4 2.75,1.4
"DO-214AC (SMA)" [mil] "Footprint for TVS"
  rect 80x80 smd: 1(-40,0) 2(130,0)
  silkscreen extent -60,-55 150,55
ECQ-E1104KF [mil] "Plastic Capacitor 5mm Lead Space"
  round 55 hole 36: 1(0,0) 2(196.85,0)
  silkscreen extent -55,-98 252,98
ECQ-E1105KF [mil] "Plastic Cap 1UF"
  round 55 hole 36: 1(0,0) 2(390,0)
  silkscreen extent -39,-132 433,132
ECQ-E1106KF_Vert [mil] "Plastic Cap 10UF, Vertically Mounted"
  round 60 hole 40: 1(0,0) 2(890,0)
  silkscreen extent -50,-225 950,225
ECQ-E1335KF [mil] "Plastic Cap 3.3UF"
  round 60 hole 40: 1(0,0) 2(590,0)
  silkscreen extent -70,-170 660,170
ECQ-E1473KF [mm] "5mm Lead Space Plastic Capacitor"
  rect 1.2x1.2 hole 0.737: 1(0,0)
  round 1.2 hole 0.737: 2(5,0)
  silkscreen extent -1.4,-2.3 6.4,2.2
HDR1X3 [mm] "Connector; Header; 3 Position"
  rect 1.5x1.5 hole 0.914: 1(0,0)
  round 1.5 hole 0.914: 2(2.54,0) 3(5.08,0)
  silkscreen extent -1.27,-1.27 6.35,1.27
LED_RA [mil]
  round 60 hole 46: 0(50,100)
  round 50 hole 36: A(-50,200) K(50,200)
  silkscreen extent -120,-75 120,350
MOLEX_156_RA_2 [mil] "2 Pin Molex, 0.156mil Spacing, Right Angle"
  rect 110x110 hole 79: 1(0,0)
  round 110 hole 79: 2(0,-156)
  silkscreen extent 213,-226 792,70
Molex_156_RA_3 [mil] "3 Pin Molex, 0.156mil Spacing, Right Angle"
  rect 110x110 hole 67: 1(0,0)
  round 110 hole 67: 2(0,-156) 3(0,-312)
  silkscreen extent 213,-382 792,70
"my LUMEX Dual LED" [mil] "Stacked Dual LED PCB Rt Angle"
  rect 40x40 hole 25: 1(0,0)
  round 40 hole 25: 2(0,-100) 3(-100,0) 4(-100,-100)
  silkscreen extent -320,-135 45,35
MY_DB9F_RA [mil]
  rect 62x62 hole 40: 1(-216,0)
  round 62 hole 40: 2(-108,0) 3(0,0) 4(108,0) 5(216,0) 6(-162,112) 7(-54,112) 8(54,112) 9(162,112)
  round 150 hole 125.9: 10(-500,56) 11(500,56)
  silkscreen extent -615,-70 615,672
MY_DB9M_RA [mil]
  rect 62x62 hole 40: 1(216,0)
  round 62 hole 40: 2(108,0) 3(0,0) 4(-108,0) 5(-216,0) 6(162,112) 7(54,112) 8(-54,112) 9(-162,112)
  round 150 hole 125.9: 10(-500,56) 11(500,56)
  silkscreen extent -615,-70 615,672
MY_TO220 [mil]
  rect 62x62 hole 40: 1(-100,0) 2(0,0) 3(100,0)
  round 200 hole 125.9: 4(0,680)
  silkscreen extent -200,60 200,800
smt_tp [mil] "Surface Mount Test Point"
  rect 165x110 smd: 1(0,0)
SO8_M [mm] "SOIC, 8-Leads, Body 4.9x3.9mm, Pitch 1.27mm, IPC Low Density"
  oval 2.5x0.7 smd: 1(-2.45,1.905) 2(-2.45,0.635) 3(-2.45,-0.635) 4(-2.45,-1.905) 5(2.45,-1.905) 6(2.45,-0.635) 7(2.45,0.635) 8(2.45,1.905)
  silkscreen extent -2.57,-2.5 0.8,2.93, body extent -2,-2.5 2,2.5, height 1.75
so8_m [mm] "SOIC, 8-Leads, Body 4.9x3.9mm, Pitch 1.27mm, IPC Low Density"
  oval 2.5x0.7 smd: 1(-2.45,1.905) 2(-2.45,0.635) 3(-2.45,-0.635) 4(-2.45,-1.905) 5(2.45,-1.905) 6(2.45,-0.635) 7(2.45,0.635) 8(2.45,1.905)
  silkscreen extent -2.57,-2.5 0.8,2.93, body extent -2,-2.5 2,2.5, height 1.75
SOD123 [mm] "SOD-123; 2 Leads; Body 2.7 x 1.6 mm, (LxW)"
  rect 1.6x0.8 smd: 1(-1.7,0) 2(1.7,0)
  silkscreen extent -1.45,-0.85 1.45,0.85
SOT89M [mm] "SOT89, 3-Leads, Body 4.5x2.4 mm, Pitch 1.5mm, Lead Span 4.1mm, IPC Low Density"
  rect 1.6x0.6 smd: 1(-1.9,1.5) 3(-1.9,-1.5)
  rect 2x0.7 smd: 2(-1.7,0)
  oct 3.4x2 smd: 2(1,0)
  silkscreen extent -2.07,-2.3 1.3,2.47, body extent -1.3,-2.3 1.3,2.3, height 1.6
SOT-223 [mil]
  rect 40x60 smd: 1(0,0) 2(90,0) 3(180,0)
  rect 130x60 smd: 4(90,248)

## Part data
C1 C2 C3 C4 C5 C6 C7 C8 C9 C10 C11 C12 C13 C14 C16 C18 C19 C21 C23 C24 C27 C28 C31 C32 C33 C35: library part MYCAP, Digikey Part Number=PCC2234CT-ND
C15 C25: library part MYCAP, Digikey Part Number=EF1105-ND
C17: library part MYCAP, Digikey Part Number=EF1106-ND
C20: library part MYCAP, Digikey Part Number=EF1335-ND
C22 C26: library part MYCAP, Digikey Part Number=EF1473-ND
C29: library part MYCAP, Digikey Part Number=P4671-ND
C30: library part MYCAP, Capacitance=100pF, Case/Package=Radial, Dielectric=PP, Manufacturer=KEMET, Manufacturer Part Number=PFR5101J100J11L4BULK, Max Operating Temperature=100°C, Min Operating Temperature=-55°C, Package Quantity=1000, Supplier Part Number 1=399-7699-ND, Tolerance=5%, Voltage=100V, Voltage Rating (AC)=63V
C34: library part "CAPACITOR POL", "Polarized Cap", Digikey Part Number=478-3075-1-ND
C36 C39 C40 C41: library part "CAPACITOR POL", "Polarized Cap", Digikey Part Number=478-1722-1-ND
C37 C38: library part MYCAP, Digikey Part Number=PCC104BCT-ND
D1: Digikey Part Number=L20051-ND
D2: library part "Dual Stacked LED", "Dual Green LED", Digikey Part Number=67-1321-ND
D3: library part TVS, "5V Bi-directional Transient Voltage Suppressor", Digikey Part Number=SMAJ6.0CALFCT-ND
D4: library part "Diode 1N4001", "1 Amp General Purpose Rectifier", Digikey Part Number=UF4007CT-ND
D5 D6: library part "Diode 1N4148", "High Conductance Fast Diode", Digikey Part Number=RB160M-60CT-ND
J1: library part "D Connector 9", "Receptacle Assembly, 9 Position, Right Angle", Digikey Part Number=A32117-ND
J2: library part "D Connector 9", "Receptacle Assembly, 9 Position, Right Angle", Digikey Part Number=A32092-ND
P1 P2: "BNC Elbow Connector", Digikey Part Number=A32244-ND
P3: "Header, 3-Pin", Digikey Part Number=609-3468-ND
P4: "Header, 3-Pin, Right Angle", Digikey Part Number=WM5236-ND
P5: "Header, 2-Pin", Digikey Part Number=WM5235-ND
Q1: "NPN General Purpose Amplifier", Digikey Part Number=PZT3904T1GOSCT-ND
Q2: "N-Channel, Enh Mode, MOSFET", Digikey Part Number=RHP020N06T100CT-ND
R1 R2 R24 R25 R35: library part Res3, "Resistor", Digikey Part Number=P1.00KFCT-ND
R3 R51: library part MYRES, Digikey Part Number=P10.0FCT-ND
R4 R21 R50: library part MYRES, Digikey Part Number=P1.00KFCT-ND
R5 R6 R7 R8 R42 R43: library part MYRES, Digikey Part Number=P10.0KFCT-ND
R9: library part MYRES, Digikey Part Number=P100FCT-ND
R10 R11 R18 R19 R30: library part Res3, "Resistor", Digikey Part Number=P0.0ECT-ND
R12 R23 R33 R36 R49: library part Res3, "Resistor", Digikey Part Number=P10.0KFCT-ND
R13 R34: library part Res3, "Resistor"
R14 R17 R20 R22 R26 R27 R28 R31: library part Res3, "Resistor", Digikey Part Number=TNP4.99KACCT-ND
R15 R16: library part MYRES
R29: library part MYRES, Digikey Part Number=P100KFCT-ND
R32: library part MYRES, Digikey Part Number=TNP4.99KACCT-ND
R37: library part MYRES, Digikey Part Number=P21.5KFCT-ND
R38 R40: library part Res3, "Resistor", Digikey Part Number=RNCS1206BKE1M00CT-ND
R39: library part MYRES, Digikey Part Number=P1.21KFCT-ND
R41: library part MYRES, Digikey Part Number=RG32P10.0KBCT-ND
R44: library part MYRES, Digikey Part Number=RG32P1.0KBCT-ND
R45: library part MYRES, Digikey Part Number=P75.0FCT-ND
R46 R55: library part MYRES, Digikey Part Number=P0.0ECT-ND
R47: library part MYRES, Digikey Part Number=RNCP1206FTD909RCT-ND
R48: library part MYRES, Digikey Part Number=P453BCCT-ND
R52: library part MYRES, Digikey Part Number=TNP249ABCT-ND
R53: library part MYRES, Digikey Part Number=P732BCCT-ND
R54: library part MYRES, Digikey Part Number=P1.0ECT-ND
TP1 TP2 TP3 TP4 TP5 TP6 TP7 TP8 TP9 TP10 TP11 TP12 TP13 TP14 TP15 TP16 TP17 TP18 TP19 TP20 TP21 TP22 TP23 TP24 TP25 TP26 TP27 TP28 TP29 TP30: "PCB Testpoint", Digikey Part Number=5016KCT-ND
U1 U8 U9 U10 U11 U12 U13 U14: "Ultra-Low Noise, Precision Operational Amplifier", Digikey Part Number=OP27GSZ-REEL7CT-ND
U2 U3: "Low power instrumentation amplifier", Digikey Part Number=AD620BR-REEL7CT-ND
U4 U6: library part AD826AR, "High-Speed, Low-Power Dual Operational Amplifier", Digikey Part Number=AD8672ARZ-ND
U5: library part LT1021, Digikey Part Number=LT1021DCS8-10-ND
U7: "Hex Inverter Buffer / Driver with Open-Collector High-Voltage Outputs", Digikey Part Number=296-14876-1-ND
U15: "Three-Terminal Adjustable Output Positive Voltage Regulator", Digikey Part Number=LM317TFS-ND

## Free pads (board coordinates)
  round 31 hole 14: 0(3190,4100) 1(1550,2995) 2(1310,5940) 3(1285,5670) 4(1210.12,5375) 5(675,5420) 6(600.12,5810.12) 7(965,5500) 8(1960,4710) 9(1955.12,5195.12) 10(1310,4745) 11(2025,5005) 12(595.12,4630.12) 13(789.88,4289.88) 14(1630,4285) 15(665,2290) 16(1050,1895) 17(535.12,5329.88) 18(535.12,5055.12) 19(1625,4925) 20(1300,5560) 21(1705,4825) 22(1290,4485) 23(968.54,4326.34) 24(1161.46,4335) 25(1205,4180) 26(1160,3910) 27(818.54,3696.46) 28(1100,3650) 29(1950,3545) 30(1700,2975) 31(1865,2605) 32(1660,3180) 33(1050,1620) 34(1288.54,1541.46) 35(1515.12,1419.88) 36(1674.88,1640.12) 37(1840,1775) 38(2075,1400) 39(2160,1610) 40(2255,1875) 41(2060,935) 42(1370,990) 43(1640,650) 44(1890,415) 45(2315,910) 46(1310,1340) 47(1390,720) 48(1615,430) 49(2710,815) 50(2460,460) 51(2753.54,1523.54) 52(2785,1830) 53(2542.5,1852.5) 54(2760,1430) 55(2585,563.54) 56(3245.94,2105.94) 57(3704,316) 58(4174,316) 59(4504,1336) 60(3670,916) 61(1165,3309.88) 62(1105,3500) 63(2440,3730) 64(2720,3920) 65(2795.12,4829.88) 66(3285,4755) 67(3450.12,5235.12) 68(3360,5020) 69(3700,5400) 70(3910,4775) 71(3599.88,4704.88) 72(3575,4230) 73(3604.88,3965.12) 74(3795,4045) 75(3038.54,4805) 76(3595,3520) 77(3550,3305) 78(3135.12,3359.88) 79(3253.54,3346.46) 80(2695,3665) 81(2715.12,4060.12) 82(3745,3690) 83(4325,3330)
  round 238 hole 193: 89(4500,300) 89(4500,5900)

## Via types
v1: diameter 31, hole 14, Top Layer to Bottom Layer, 10 vias

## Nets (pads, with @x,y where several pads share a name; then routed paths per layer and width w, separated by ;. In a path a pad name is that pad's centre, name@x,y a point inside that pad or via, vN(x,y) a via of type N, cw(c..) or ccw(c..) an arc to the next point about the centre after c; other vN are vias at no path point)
+15: C1.1 C2.2 C6.2 C7.2 C8.1 C9.1 C12.2 C18.2 C19.2 C21.2 C28.2 C33.2 C34.1 C35.2 C38.1 C41.1 D1.A D5.2 P4.1 pad.3 pad.11 pad.17 pad.22 pad.26 pad.33 pad.37 pad.45 pad.47 pad.53 pad.62 pad.64 pad.68 pad.72 pad.74 pad.76 R2.2 TP23.1 U1.7 U2.7 U3.7 U4.8 U5.2 U6.8 U8.7 U9.7 U10.7 U11.7 U12.7 U13.7 U14.7 U15.3 | length 4167.4
  Top Layer w20: R2.2 pad.17 ; U1.7 1135,3885 1205,3955 C7.2 ; C2.2 pad.33 1080,1590 U4.8 ; C1.1 1075,3470 pad.62 U5.2 ; U2.7 pad.22 1310,4505 C8.1 ; U3.7 pad.3 1310,5695 C9.1 ; U6.8 C6.2@1390,779.88 ; pad.37 1785.12,1720.12 C12.2 1845,1650.12 U9.7 ; U8.7 2015,4995 2040,5020 C18.2 ; C19.2 2290,935 2375,850 U10.7 ; C21.2 2520,1875 2565,1830 U11.7 ; U12.7 2760.12,3920 C28.2 ; U13.7 3325,4985 pad.68 C33.2 ; U14.7 3625,3520 3650,3545 C35.2 ; TP23.1 C41.1 P4.1 C38.1 ; pad.72 3593.07,4211.93 D5.2 ; C34.1 pad.74
-15: C3.2 C4.1 C5.1 C10.2 C13.2 C14.2 C16.2 C23.2 C24.2 C27.2 C31.2 C32.2 C36.2 C37.1 P4.3 pad.7 pad.18 pad.21 pad.23 pad.27 pad.38 pad.46 pad.48 pad.51 pad.55 pad.58 pad.63 pad.75 pad.79 R1.1 TP21.1 U1.4 U2.4 U3.4 U4.4 U6.4 U8.4 U9.4 U10.4 U11.4 U12.4 U13.4 U14.4 | length 3279.4
  Top Layer w20: pad.18 R1.1 ; U1.4 pad.27 865,3650 C3.2 ; U3.4@965,5570 965,5465 990,5440 C5.1 ; U2.4 pad.23 C4.1 ; U4.4@1238.54,1340 C10.2 ; U6.4 C13.2@1686.34,428.54 ; 1705,4880.46 1705,4790 1720,4775 C14.2 ; U9.4 2048.54,1363.54 2075,1390 C16.2 ; U12.4 2440,3818.54 2440,3675 2450,3665 C23.2 ; U10.4 2593.54,563.54 2620,590 C24.2 ; U11.4 pad.51 2785,1555 C27.2 ; U13.4 3038.54,4761.46 3045,4755 C31.2 ; U14.4 pad.79 3295,3305 C32.2 ; TP21.1 3891,501 3975.12,585.12 C37.1 ; C37.1@3978.12,764 P4.3 ; C36.2 pad.58
GND: C1.2 C2.1 C3.1 C4.2 C5.2 C6.1 C7.1 C8.2 C9.2 C10.1 C11.2 C12.1 C13.1 C14.1 C15.2 C16.1 C18.1 C19.1 C20.2 C21.1 C23.1 C24.1 C25.2 C27.1 C28.1 C31.1 C32.1 C33.1 C34.2 C35.1 C36.1 C37.2 C38.2 C39.2 C40.2 C41.2 D2.2 D2.3 D3.2 D4.1 J1.10 J1.11 J2.10 J2.11 P1.2 P4.2 P5.2 pad.2 pad.4 pad.5 pad.6 pad.8 pad.9 pad.10 pad.12 pad.13 pad.14 pad.15 pad.16 pad.19 pad.20 pad.24 pad.25 pad.28 pad.29 pad.30 pad.31 pad.32 pad.34 pad.35 pad.36 pad.39 pad.40 pad.41 pad.42 pad.43 pad.44 pad.49 pad.50 pad.52 pad.54 pad.56 pad.57 pad.59 pad.60 pad.61 pad.65 pad.66 pad.67 pad.69 pad.70 pad.71 pad.73 pad.77 pad.78 pad.80 pad.81 pad.82 pad.83 Q2.3 R5.1 R6.1 R7.1 R8.1 R9.1 R12.2 R34.2 R47.2 R49.2 R53.1 TP11.1 TP22.1 TP28.1 TP30.1 U2.5 U3.5 U4.5 U5.4 U6.5 U7.7 U7.9 U7.11 U7.13 U8.3 U9.3 U10.3 U11.3 | length 6942.8
  Top Layer w20: pad.12 R6.1 ; pad.6 R8.1 ; pad.15 R9.1 D3.2@754.88,2574.88 ; pad.5 R7.1 ; R5.1 pad.13 ; D3.2 765,2585 935.12,2585 R12.2 ; C3.1 pad.28 ; C2.1 pad.16 ; C1.2 1219.88,3309.88 1243.54,3333.54 U5.4 ; C5.2 pad.4 ; C4.2@1161.46,4286.34 U2.5 ; U3.5 1290,5570 pad.20 ; C7.1 pad.25 ; U4.5 pad.34 ; C8.2 pad.10 ; C9.2 pad.2 ; C6.1 pad.42 ; C10.1 pad.35 ; U6.5 1611.46,621.46 pad.43 ; U7.13 1600,2950 1625,2975 pad.30 ; pad.19 1645,4945 U8.3 ; pad.14 TP11.1@1755,4285 ; C11.2@1660.12,3090 pad.32@1660.12,3180 ; pad.36 C12.1 ; U7.11 pad.30 ; U7.9 1800,2955 1780,2975 pad.30 ; C13.1 pad.44 ; U7.7 1850,2620 pad.31 ; C14.1 1895,4775 pad.8 ; U9.3 1895,1425 1930,1460 1980,1460 2000,1480 2000,1570 2015.12,1585.12 C16.1 2135.12,1585.12 pad.39@2165,1615 ; pad.29 R34.2 ; pad.9 C18.1 ; pad.41 C19.1 ; pad.40 C21.1 ; U10.3 2425,495 pad.50 ; U11.3 2615,1460 2645,1430 pad.54 ; C24.1 2645.12,750.12 pad.49 ; C23.1 pad.80 ; pad.81 C28.1 ; C27.1 pad.52 ; pad.65 R47.2 ; R49.2 pad.78 ; C31.1 pad.66 ; pad.56 Q2.3 ; C33.1 pad.67 ; C32.1 pad.77 ; TP22.1 pad.60 ; R53.1 pad.71 ; pad.73 C34.2 ; C35.1 3724.88,3710.12 3785,3650 C39.2 ; pad.69 TP28.1 ; pad.57 C36.1 ; C37.2 C38.2 ; 3869.88,920 P4.2 ; pad.70 C40.2 ; pad.83 TP30.1 ; C41.2 pad.59
NetC15_1: C15.1 R39.1 U12.3 | length 365.9
  Top Layer w20: C15.1 2270,3710 2300.12,3740.12 R39.1 U12.3
NetC17_1: C17.1 R37.1 R39.2 | length 604.6
  Top Layer w20: C17.1@2060.12,4344.88 R37.1 R39.2
NetC17_2: C17.2 R43.1 TP18.1 U12.2 U12.6 | length 1839.5
  Top Layer w20: U12.2 2490,3920 2540,3870 U12.6 2805,3870 ; R43.1 2510,3510 2570,3570 2755,3570 2805,3620 2805,3870 ; C17.2 2950,4155 3015,4090 TP18.1 2805,3870
NetC20_1: C20.1 R42.1 R43.2 | length 1049.3
  Top Layer w20: R42.1@2330,2275.12 C20.1 2330,2710 2510,2890 R43.2
NetC22_1: C22.1 R35.2 TP14.1 U8.6 | length 879.4
  Top Layer w20: R35.2 1810.12,4979.88 1845,4945 U8.6 TP14.1 C22.1
NetC22_2: C22.2 C26.1 R48.2 | length 412.2
  Top Layer w20: C22.2 C26.1@2718.15,5141.85 ; C26.1 2870,5140 2879.88,5149.88 R48.2
NetC25_1: C25.1 C30.2 D4.2 R42.2 R51.2 | length 1245.8
  Top Layer w20: R42.2 2680,2275 2735,2330 C25.1 2880,2440 2898.15,2458.15 C30.2 3216.85,2595 R51.2 ; D4.2 2599.09,2274.09
NetC26_2: C26.2 R47.1 U13.3 | length 310.4
  Top Layer w20: C26.2 R47.1@2886.97,4943.15 ; R47.1@2895.12,4935 U13.3
NetC29_1: C29.1 R40.1 R51.1 R54.2 R55.1 TP26.1 | length 4197.6
  Top Layer w20: R40.1 2949.88,274.88 3110,435 C29.1 3110,1525 3165,1580 3755,1580 3815,1640 3815,2205 3749.88,2270.12 R54.2 R55.1@3615,2594.88 ; R51.1 R55.1 3614.88,2864.88 TP26.1
NetC29_2: C29.2 R44.2 | length 238
  Top Layer w20: R44.2 C29.2
NetC30_1: C30.1 R45.1 | length 424.9
  Top Layer w20: C30.1 R45.1@3080,3079.88
NetC40_1: C40.1 D6.1 R52.1 R53.2 U15.1 | length 1508.6
  Top Layer w20: R52.1 R53.2 ; R52.1@3715.12,4470 U15.1 4060,4470 4125,4535 4125,5075 4080,5120 C40.1 ; D6.1 R52.1@3726.93,4448.19
NetD1_K: D1.K Q1.2 Q1.4 | length 1214.9
  Top Layer w20: D1.K 470,2300 728,2042 Q1.4 Q1.2
NetD2_1: D2.1 R2.1 | length 134.9
  Top Layer w20: D2.1 R2.1@409.88,5245
NetD2_4: D2.4 R1.2 | length 397.6
  Top Layer w20: D2.4 175,5110 255,5030 390,5030 424.88,5064.88 R1.2
NetD3_1: D3.1 P3.3 R3.2 R12.1 R13.2 TP1.1 U7.1 | length 2237.8
  Top Layer w20: D3.1 TP1.1@760,3125 ; R3.2 R13.2@980.12,2895 ; R13.2 R12.1 1084.88,2745.12 v1(1085,2745) ; P3.3 U7.1
  Bottom Layer w20: v1(1085,2745) 1125,2705 1125,2345 1260,2210 P3.3
NetJ1_1: J1.1 R18.2 | length 1406.1
  Top Layer w20: J1.1 556,1284 605,1235 605,565 740,430 R18.2
NetJ1_2: J1.2 R10.2 | length 377.3
  Top Layer w20: J1.2 653,1392 695,1350 R10.2
NetJ1_6: J1.6 R19.2 | length 1366.8
  Top Layer w20: J1.6 602,1338 660,1280 660,765 795,630 R19.2
NetJ1_7: J1.7 R11.2 | length 510.8
  Top Layer w20: J1.7 566,1446 660,1540 R11.2
NetJ2_1: J2.1 R6.2 U2.3 | length 569.8
  Top Layer w20: J2.1 R6.2@686.12,4516 ; R6.2 810.12,4519.88 895,4435 U2.3
NetJ2_6: J2.6 R5.2 U2.2 | length 1363.1
  Top Layer w20: R5.2 604.88,4400.12 543,4462 J2.6 318,4558 475,4715 770,4715 835,4650 835,4550 900,4485 U2.2
NetP1_1: P1.1 R3.1 | length 164.9
  Top Layer w20: P1.1@485,2895 R3.1
NetP2_1: P2.1 R8.2 U3.3 | length 541.5
  Top Layer w20: P2.1 R8.2@674.88,5700 ; R8.2 679.88,5695 775,5695 850,5620 U3.3
NetP2_2: P2.2 R7.2 U3.2 | length 1752.5
  Top Layer w20: R7.2@673.54,5601.57 480,5601.57 480,5535 444.21,5499.21 279.21,5499.21 279.21,5900.79 764.21,5900.79 810,5855 810,5735 875,5670 U3.2
NetP3_1: P3.1 R36.2 TP12.1 U7.2 | length 1310.6
  Top Layer w20: U7.2 1600,2125 1635,2090 1700,2090 1750,2140 P3.1 TP12.1@2010,2210 ; TP12.1@1995,2225 R36.2
NetP3_2: P3.2 U7.3 U7.5 | length 1047.3
  Top Layer w20: P3.2 U7.3 ; U7.5 1750,2645 v1(1780,2615)
  Bottom Layer w20: P3.2 1650,2300 1780,2430 v1(1780,2615)
NetP5_1: P5.1 R55.2 TP29.1 | length 414.9
  Top Layer w20: R55.2 TP29.1 P5.1
NetQ1_1: Q1.1 R21.2 | length 364.7
  Top Layer w20: Q1.1 1150,2410 1210,2470 R21.2
NetQ1_3: Q1.3 R9.2 | length 104.9
  Top Layer w20: R9.2 Q1.3
NetQ2_1: Q2.1 R33.2 TP20.1 U7.4 | length 2531.9
  Top Layer w20: U7.4 1700,2610 1719.88,2590.12 R33.2 1719.88,2410.12 1800,2330 v1(1850,2330) ; v1(1850,2075) 1920,2005 3075,2005 3155,2085 3155,2160 3219.06,2224.06 Q2.1 TP20.1@3325.2,2400.2
  Bottom Layer w20: v1(1850,2075) v1(1850,2330)
NetQ2_2: Q2.2 R54.1 TP25.1 | length 420.4
  Top Layer w20: Q2.2@3444.49,2159.88 R54.1 TP25.1@3615,1910
NetR4_1: R4.1 U1.2 | length 153.4
  Top Layer w20: R4.1@665.12,3885 U1.2
NetR4_2: R4.2 R30.1 TP6.1 U1.6 | length 928.6
  Top Layer w20: R4.2 899.88,3995.12 920,3975 920,3860 945,3835 U1.6 TP6.1@1280,3835 ; TP6.1@1315,3870 R30.1
NetR10_1: R10.1 R14.2 TP3.1 U4.1 | length 876.4
  Top Layer w20: TP3.1 870,1145 900.12,1175.12 R10.1 ; R10.1@901.57,1348.54 U4.1 1080,1260 1045,1225 1045,1085 1075.12,1054.88 R14.2
NetR11_1: R11.1 R20.2 TP4.1 U4.7 | length 1040.4
  Top Layer w20: TP4.1 840,1790 900.12,1729.88 R11.1 990,1540 1020,1510 1020,1485 1055,1450 1105,1450 1130,1475 U4.7 1130,1780 1150.12,1800.12 R20.2
NetR14_1: R14.1 R22.2 U4.2 | length 308.4
  Top Layer w20: U4.2 R14.1 R22.2
NetR15_1: R15.1 U2.8 | length 154.2
  Top Layer w20: R15.1 1115.12,4604.88 1161.46,4558.54 U2.8
NetR15_2: R15.2 U2.1 | length 150.1
  Top Layer w20: U2.1 970,4536.46 970,4565 1004.88,4599.88 R15.2
NetR16_1: R16.1 U3.8 | length 164.2
  Top Layer w20: R16.1 1135.12,5799.88 1181.46,5753.54 U3.8
NetR16_2: R16.2 U3.1 | length 160.1
  Top Layer w20: U3.1 990,5721.46 990,5760 1024.88,5794.88 R16.2
NetR17_1: R17.1 R28.2 U6.2 | length 324.1
  Top Layer w20: R17.1 R28.2 1490,280 1440,330 U6.2
NetR17_2: R17.2 R18.1 TP5.1 U6.1 | length 1018
  Top Layer w20: TP5.1 1165,210 1200.12,245.12 R18.1 U6.1@1388.54,430 ; R17.2 1315.12,119.88 1280,155 1280,275 1315,310 1360,310 1390,340 U6.1
NetR19_1: R19.1 R27.2 TP2.1 U6.7 | length 1110
  Top Layer w20: TP2.1 1160,875 1200.12,834.88 R19.1 1295,630 1315,610 1315,575 1355,535 1415,535 1440,560 U6.7 1440,890 1460.12,910.12 R27.2
NetR20_1: R20.1 R26.2 U4.6 | length 370.1
  Top Layer w20: U4.6 R20.1@1180,1664.88 ; R20.1 1264.88,1689.88 1285,1710 1285,1780 1305.12,1800.12 R26.2
NetR21_1: R21.1 R23.2 U7.6 | length 842.7
  Top Layer w20: R21.1@1209.88,2740.24 R23.2 ; R21.1 1370.12,2740.12 1435,2805 1760,2805 1800,2765 U7.6
NetR22_1: R22.1 R26.1 R29.2 TP13.1 U4.3 U9.6 | length 2110.3
  Top Layer w20: R22.1 1319.88,1054.88 1345,1080 1345,1215 1310,1250 1205,1250 1180,1275 U4.3 1180,1415 1215,1450 1330,1450 1365,1485 R26.1 1480.12,1689.88 1510,1660 1510,1530 1569.88,1470.12 R29.2 1880.12,1470.12 1895,1485 U9.6 1895,1720 1950,1775 TP13.1
NetR24_1: R24.1 TP7.1 U2.6 | length 838.4
  Top Layer w20: U2.6 TP7.1 ; TP7.1@1439.88,4460.12 R24.1
NetR24_2: R24.2 R25.1 R35.1 U8.2 | length 498.4
  Top Layer w20: R35.1 1560,5180 1550.12,5170.12 R25.1 R24.2 U8.2
NetR25_2: R25.2 TP8.1 U3.6 | length 768.4
  Top Layer w20: U3.6 TP8.1 ; R25.2 TP8.1@1439.88,5584.88
NetR27_1: R27.1 R31.2 U6.6 | length 288.4
  Top Layer w20: U6.6 R27.1@1490,779.88 ; R27.1 R31.2
NetR28_1: R28.1 R31.1 R38.2 TP15.1 U6.3 U10.6 | length 2794.4
  Top Layer w20: R28.1 1574.88,119.88 1615,160 1615,285 1575,325 1510,325 1490,345 U6.3 1490,495 1530,535 1695,535 1815.12,655.12 R38.2 2405.12,655.12 2425,675 U10.6 TP15.1 2385,1035 2385,1040 1705,1040 1640,975 R31.1
NetR29_1: R29.1 R32.1 U9.2 | length 483.9
  Top Layer w20: R29.1 1665,1245 1715,1195 R32.1 ; R32.1@1845,1195.12 U9.2
NetR30_2: R30.2 R34.1 R37.2 TP10.1 | length 459.5
  Top Layer w20: R30.2 TP10.1 R37.2 ; R34.1 R37.2@1950,3869.88
NetR32_2: R32.2 R41.2 TP17.1 U11.6 | length 1717.1
  Top Layer w20: R32.2 2130,1195 2225,1290 2225,1560 2275.12,1610.12 R41.2 2580.12,1610.12 2615,1645 U11.6 2615,1805 2680,1870 2970,1870 3020,1820 TP17.1
NetR33_1: R33.1 R50.2 TP27.1 U14.6 | length 3172.9
  Top Layer w20: R33.1 1895,2505 v1(1900,2510) ; v1(2640,3005) 2840,3005 3020,3185 3735,3185 3815,3265 TP27.1 U14.6 3380,3470 3360.12,3489.88 R50.2
  Bottom Layer w20: v1(1900,2510) 2395,3005 v1(2640,3005)
NetR38_1: R38.1 R40.2 U10.2 | length 487.8
  Top Layer w20: R38.1 2205,420 2239.88,385.12 R40.2 U10.2
NetR41_1: R41.1 R44.1 U11.2 | length 492.7
  Top Layer w20: R41.1 2375,1385 2410,1350 R44.1 U11.2@2564.88,1523.43
NetR45_2: R45.2 R48.1 TP24.1 U13.2 U13.6 | length 4044.9
  Top Layer w20: R48.1 2990.12,5095.12 2950,5055 2950,5015 2980,4985 U13.2 3110,4985 3160,4935 U13.6 TP24.1 3670,4935 3710,4895 3710,4795 3810,4695 v1(3950,4695) ; R45.2 3875,3080 4240,3445 v1(4240,4070)
  Bottom Layer w20: v1(3950,4695) 4165,4695 4240,4620 v1(4240,4070)
NetR46_1: R46.1 TP9.1 U1.3 U5.6 | length 2980.4
  Top Layer w20: U1.3 870,3835 910,3795 910,3755 940,3725 1580,3725 1655,3650 TP9.1 ; U5.6 TP9.1 ; v1(2415,3180) 1775,3180 1655,3300 TP9.1 ; v1(2635,3180) 2880,3180 2930,3230 R46.1
  Bottom Layer w20: v1(2415,3180) v1(2635,3180)
NetR46_2: R46.2 R49.1 TP16.1 U14.3 | length 493.3
  Top Layer w20: TP16.1@2760.12,3470.12 R46.2 ; R46.2@2930.12,3470 U14.3
NetR50_1: R50.1 U14.2 | length 339.1
  Top Layer w20: R50.1 3175,3695 3155,3675 3155,3550 3185,3520 U14.2
VCC: C11.1 C39.1 D5.1 D6.2 pad.0 pad.1 R13.1 R23.1 R36.1 R52.2 TP19.1 U7.14 U15.2 | length 3756.6
  Top Layer w20: R13.1 1284.88,3010.12 1320.12,2974.88 R23.1 1545.51,2885 U7.14 pad.1 C11.1@1550,3089.88 ; 1550,3020 1890,3020 1995,2915 R36.1 ; pad.0@3190,4090 TP19.1 3310,4200 3413.86,4303.86 D6.2@3593.07,4303.86 ; R52.2@3593.07,4458.19 D6.2 D6.2@3593.07,4303.86 ; U15.2 4025,4370 4080,4315 4080,3965 4015,3900 C39.1 3900,4100 3830,4170 D5.1 D6.2@3593.07,4303.86
pads on no net: D1.0 J1.3 J1.4 J1.5 J1.8 J1.9 J2.2 J2.3 J2.4 J2.5 J2.7 J2.8 J2.9 U1.1 U1.5 U1.8 U5.1 U5.3 U5.5 U5.7 U5.8 U7.8 U7.10 U7.12 U8.1 U8.5 U8.8 U9.1 U9.5 U9.8 U10.1 U10.5 U10.8 U11.1 U11.5 U11.8 U12.1 U12.5 U12.8 U13.1 U13.5 U13.8 U14.1 U14.5 U14.8 U15.4

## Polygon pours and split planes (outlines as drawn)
GND on Internal Plane 1 (split plane): 4779.9,20.1 20.1,20.1 20.1,6179.9 4779.9,6179.9
VCC on Internal Plane 2 (split plane): 4779.9,20.1 20.1,20.1 20.1,6179.9 4779.9,6179.9
+15 on Internal Plane 3 (split plane): 4779.9,20.1 20.1,20.1 20.1,6179.9 4779.9,6179.9
-15 on Internal Plane 4 (split plane): 4779.9,20.1 20.1,20.1 20.1,6179.9 4779.9,6179.9

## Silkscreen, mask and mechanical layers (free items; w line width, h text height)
Top Overlay:
  rectangle: 1810,5710 3060,6085
  lines w10: -1590,5700 -370,5700 ; -1560,4300 -245,4300 ; -1525,2900 -655,2900 ; -1510,1500 -255,1500 ; -1475,2350 -100,2350 ; -1295,5200 -55,5200 ; 1465,2115 1515,2115 1515,1965 1660,1965 1660,2115 1720,2115 ; 1505,2295 1525,2315 1655,2315 1675,2295 ; 4535,1740 4585,1740 4670,1655 4670,1195 ; 4635,1230 4670,1195 ; 4705,1230 4670,1195
  text "Dither In" at 65,6035 h60
  text "OMC LV Driver" at 3190,6010 h60
  text "SN" at 1630,5985 h60
  text "D1300024-v1" at 3190,5890 h60
  text "GND" at 3725,5230 h60
  text "PWR (+ TOP)" at 220,4955 h60
  text "GND" at 1705,4140 h60
  text "From DAC" at 600,4075 h60 r90
  text "Trigger In" at 25,3245 h60
  text "GND" at 4340,3150 h60
  text "Fault" at 55,2495 h60
  text "To Piezo" at 4155,2225 h60
  text "1" at 1380,2090 h60
  text "Fault" at 1235,1960 h60
  text "PWR INPUT" at 3995,1780 h60
  text "+/- 15VDC" at 3990,1665 h60
  text "+15" at 3285,1310 h60
  text "To ADC" at 615,1260 h60 r90
  text "GND" at 3275,890 h60
  text "-15" at 3270,465 h60
Mechanical 1:
  lines w10: 0,0 4800,0 4800,6200 0,6200 0,200 0,0

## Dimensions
-370,5700 to 0,6200 on Top Overlay
-1590,5700 to -1295,5200 on Top Overlay
-1295,5200 to -1560,4300 on Top Overlay
-1525,2900 to -1560,4300 on Top Overlay
-1475,2350 to -1525,2900 on Top Overlay
-1510,1500 to -1475,2350 on Top Overlay
-1510,1500 to 0,0 on Top Overlay
-1010,0 to -890,6200 on Top Overlay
